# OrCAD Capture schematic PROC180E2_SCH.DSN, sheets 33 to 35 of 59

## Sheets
33 13. SOC POWER SUPPLY PMIC - 1: size C; title: SOC POWER SUPPLY PMIC - 1
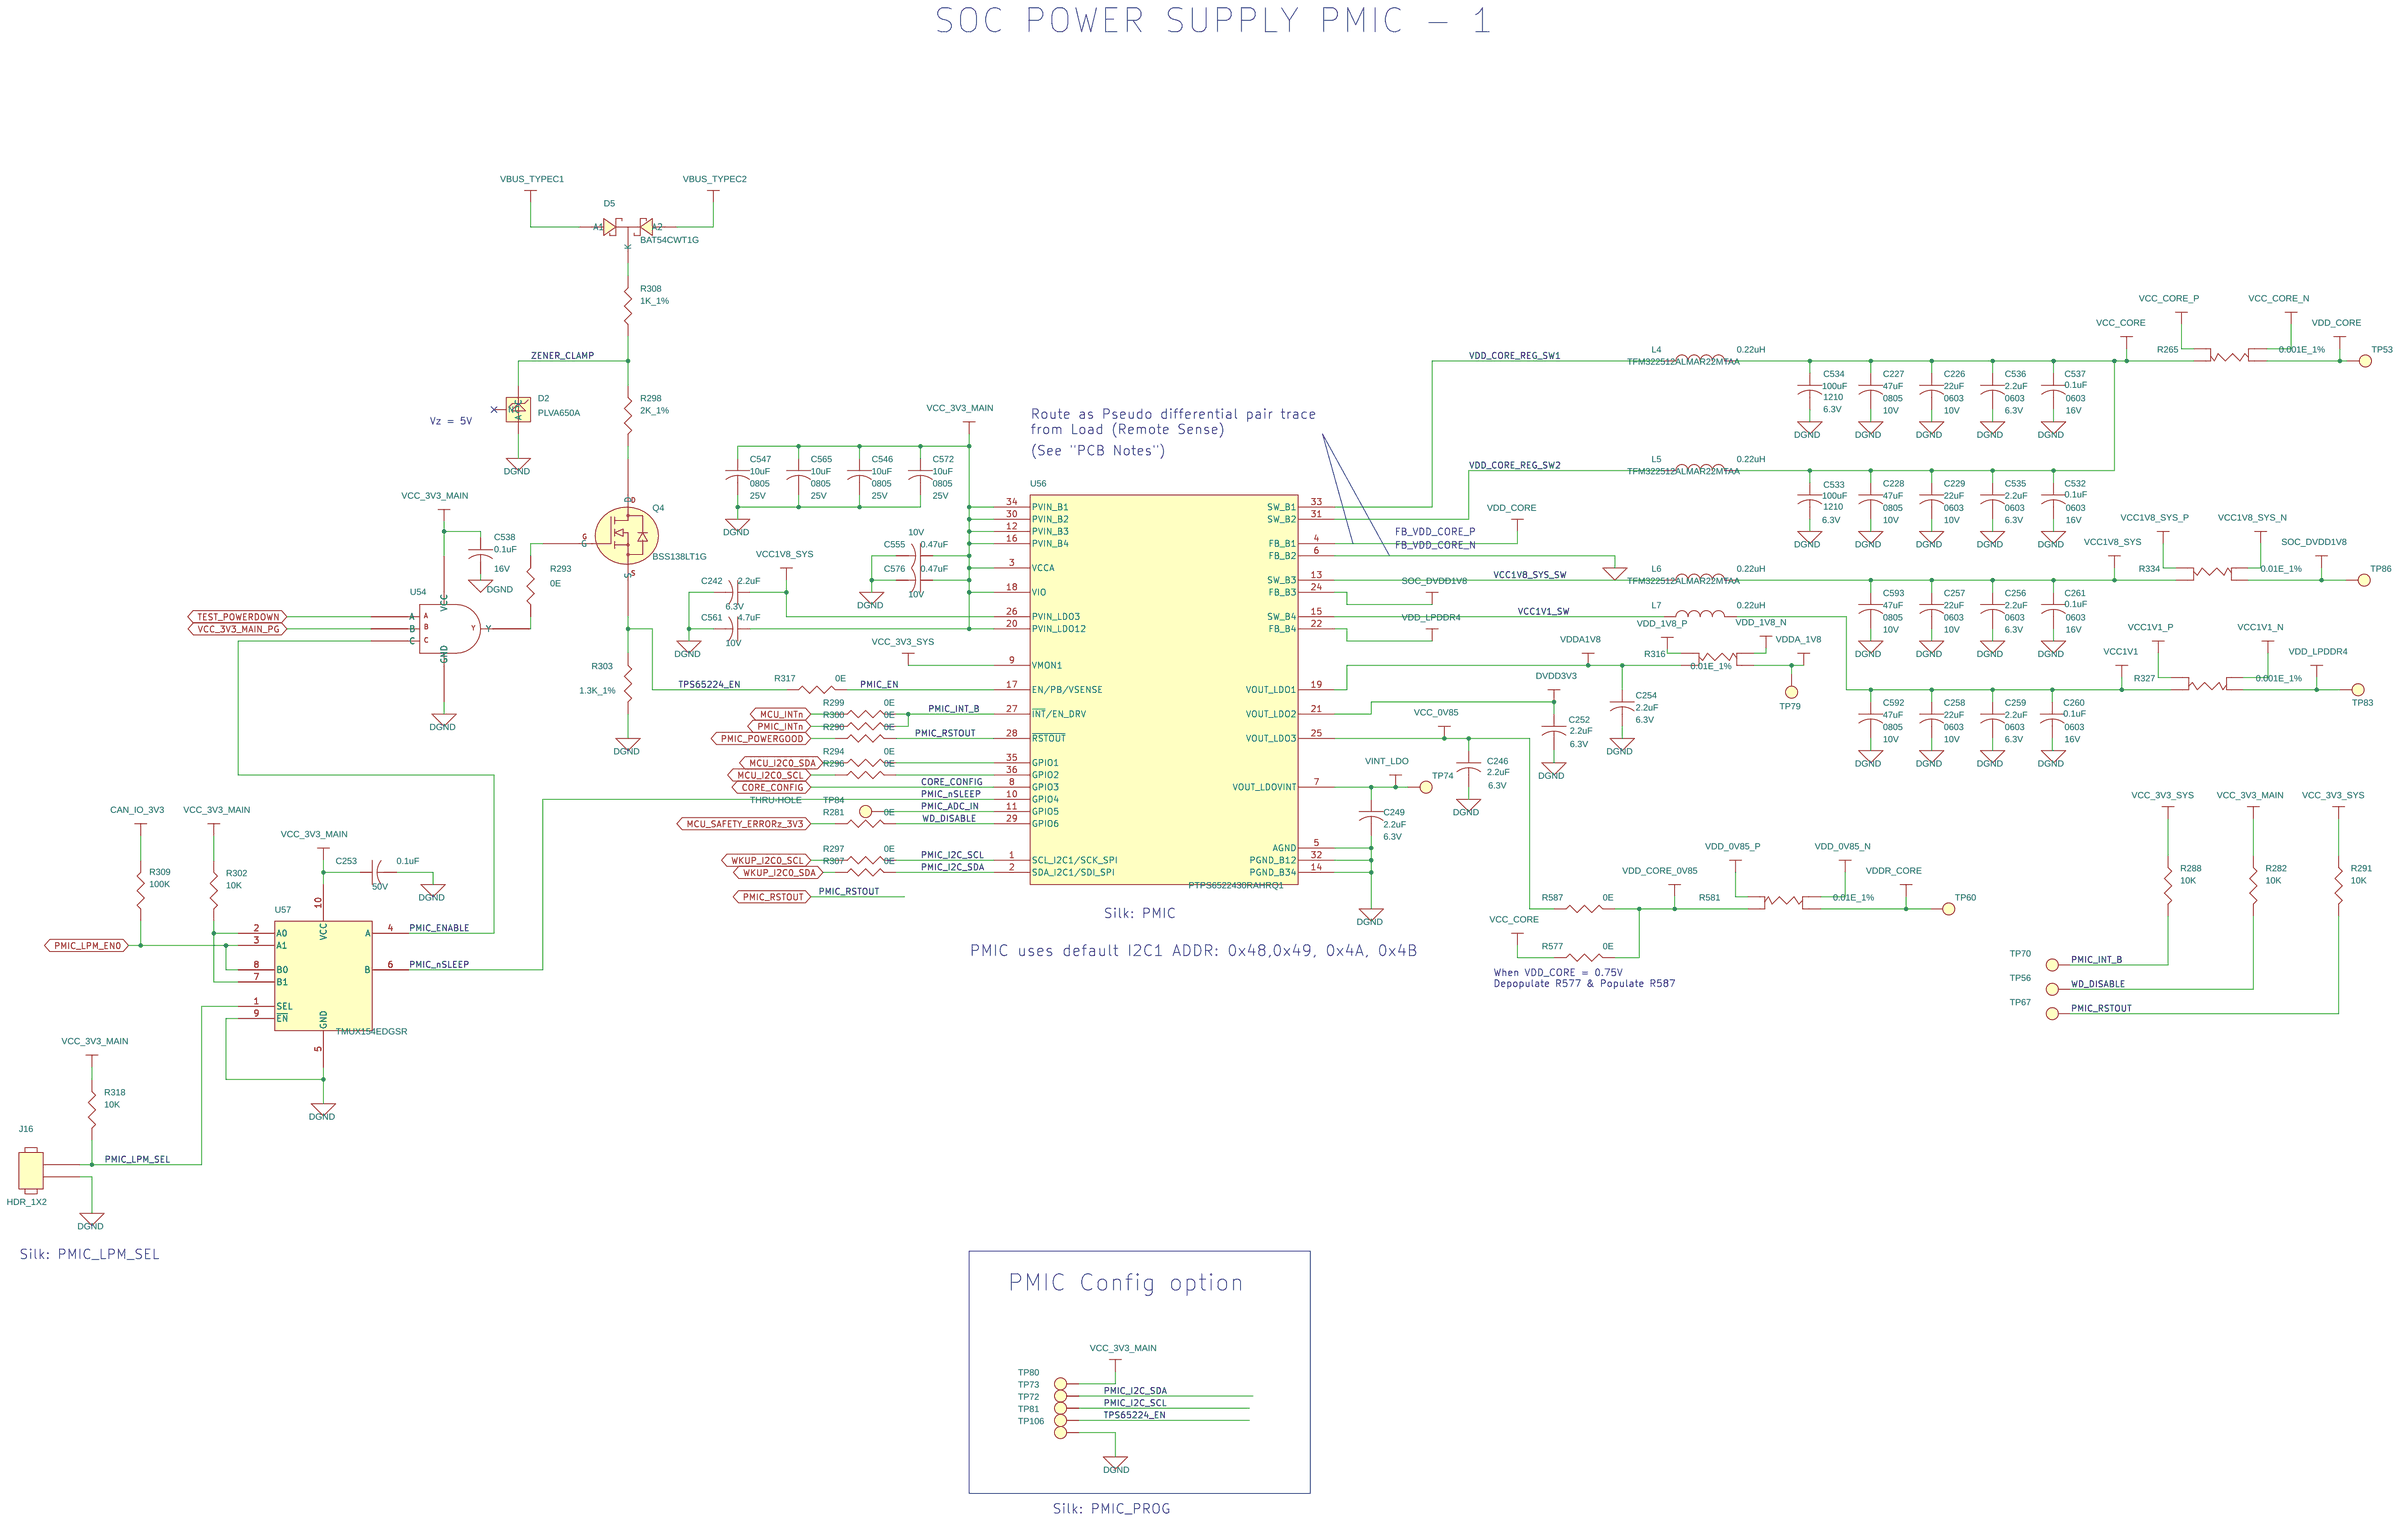
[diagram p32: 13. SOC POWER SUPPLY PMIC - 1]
34 16. SOC POWER SUPPLIES AND SUPP: size C; title: SOC POWER SUPPLIES, SUPPLY RAILS AND SOC GROUND VSS
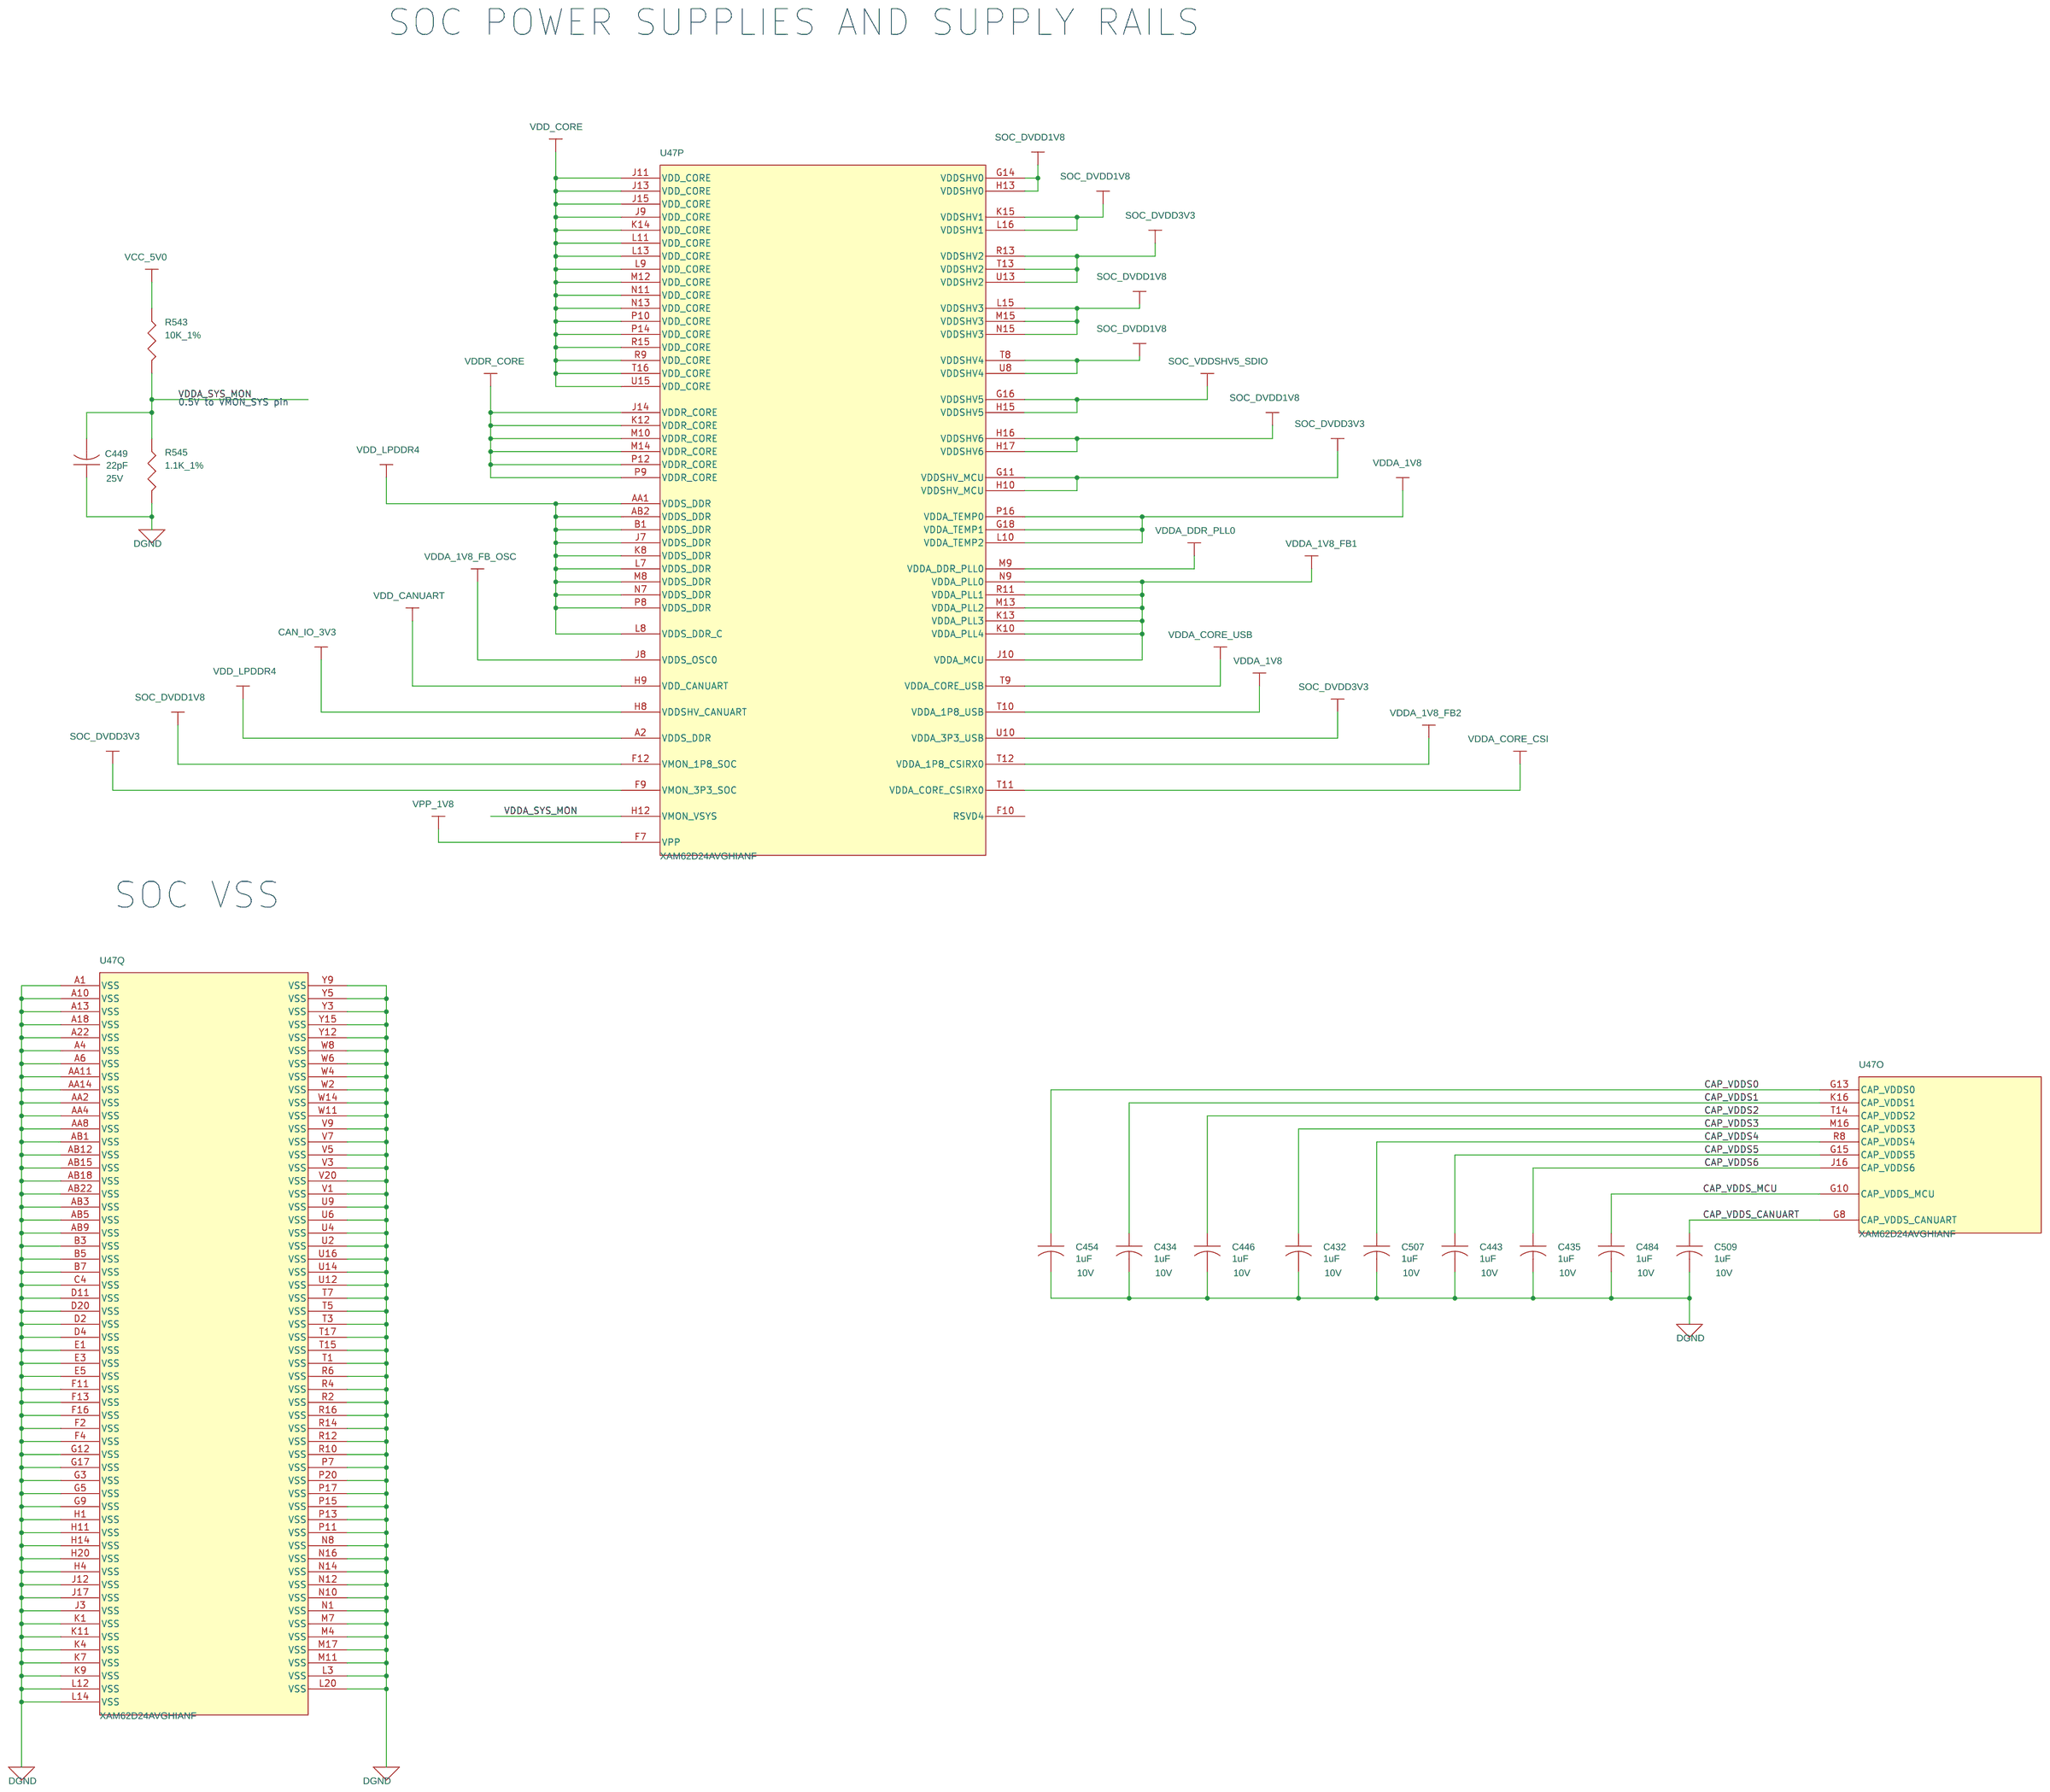
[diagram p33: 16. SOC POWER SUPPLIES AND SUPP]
35 17. SOC POWER SUPPLIES - DECAPS: size C; title: SOC POWER SUPPLIES - DECAPS 1
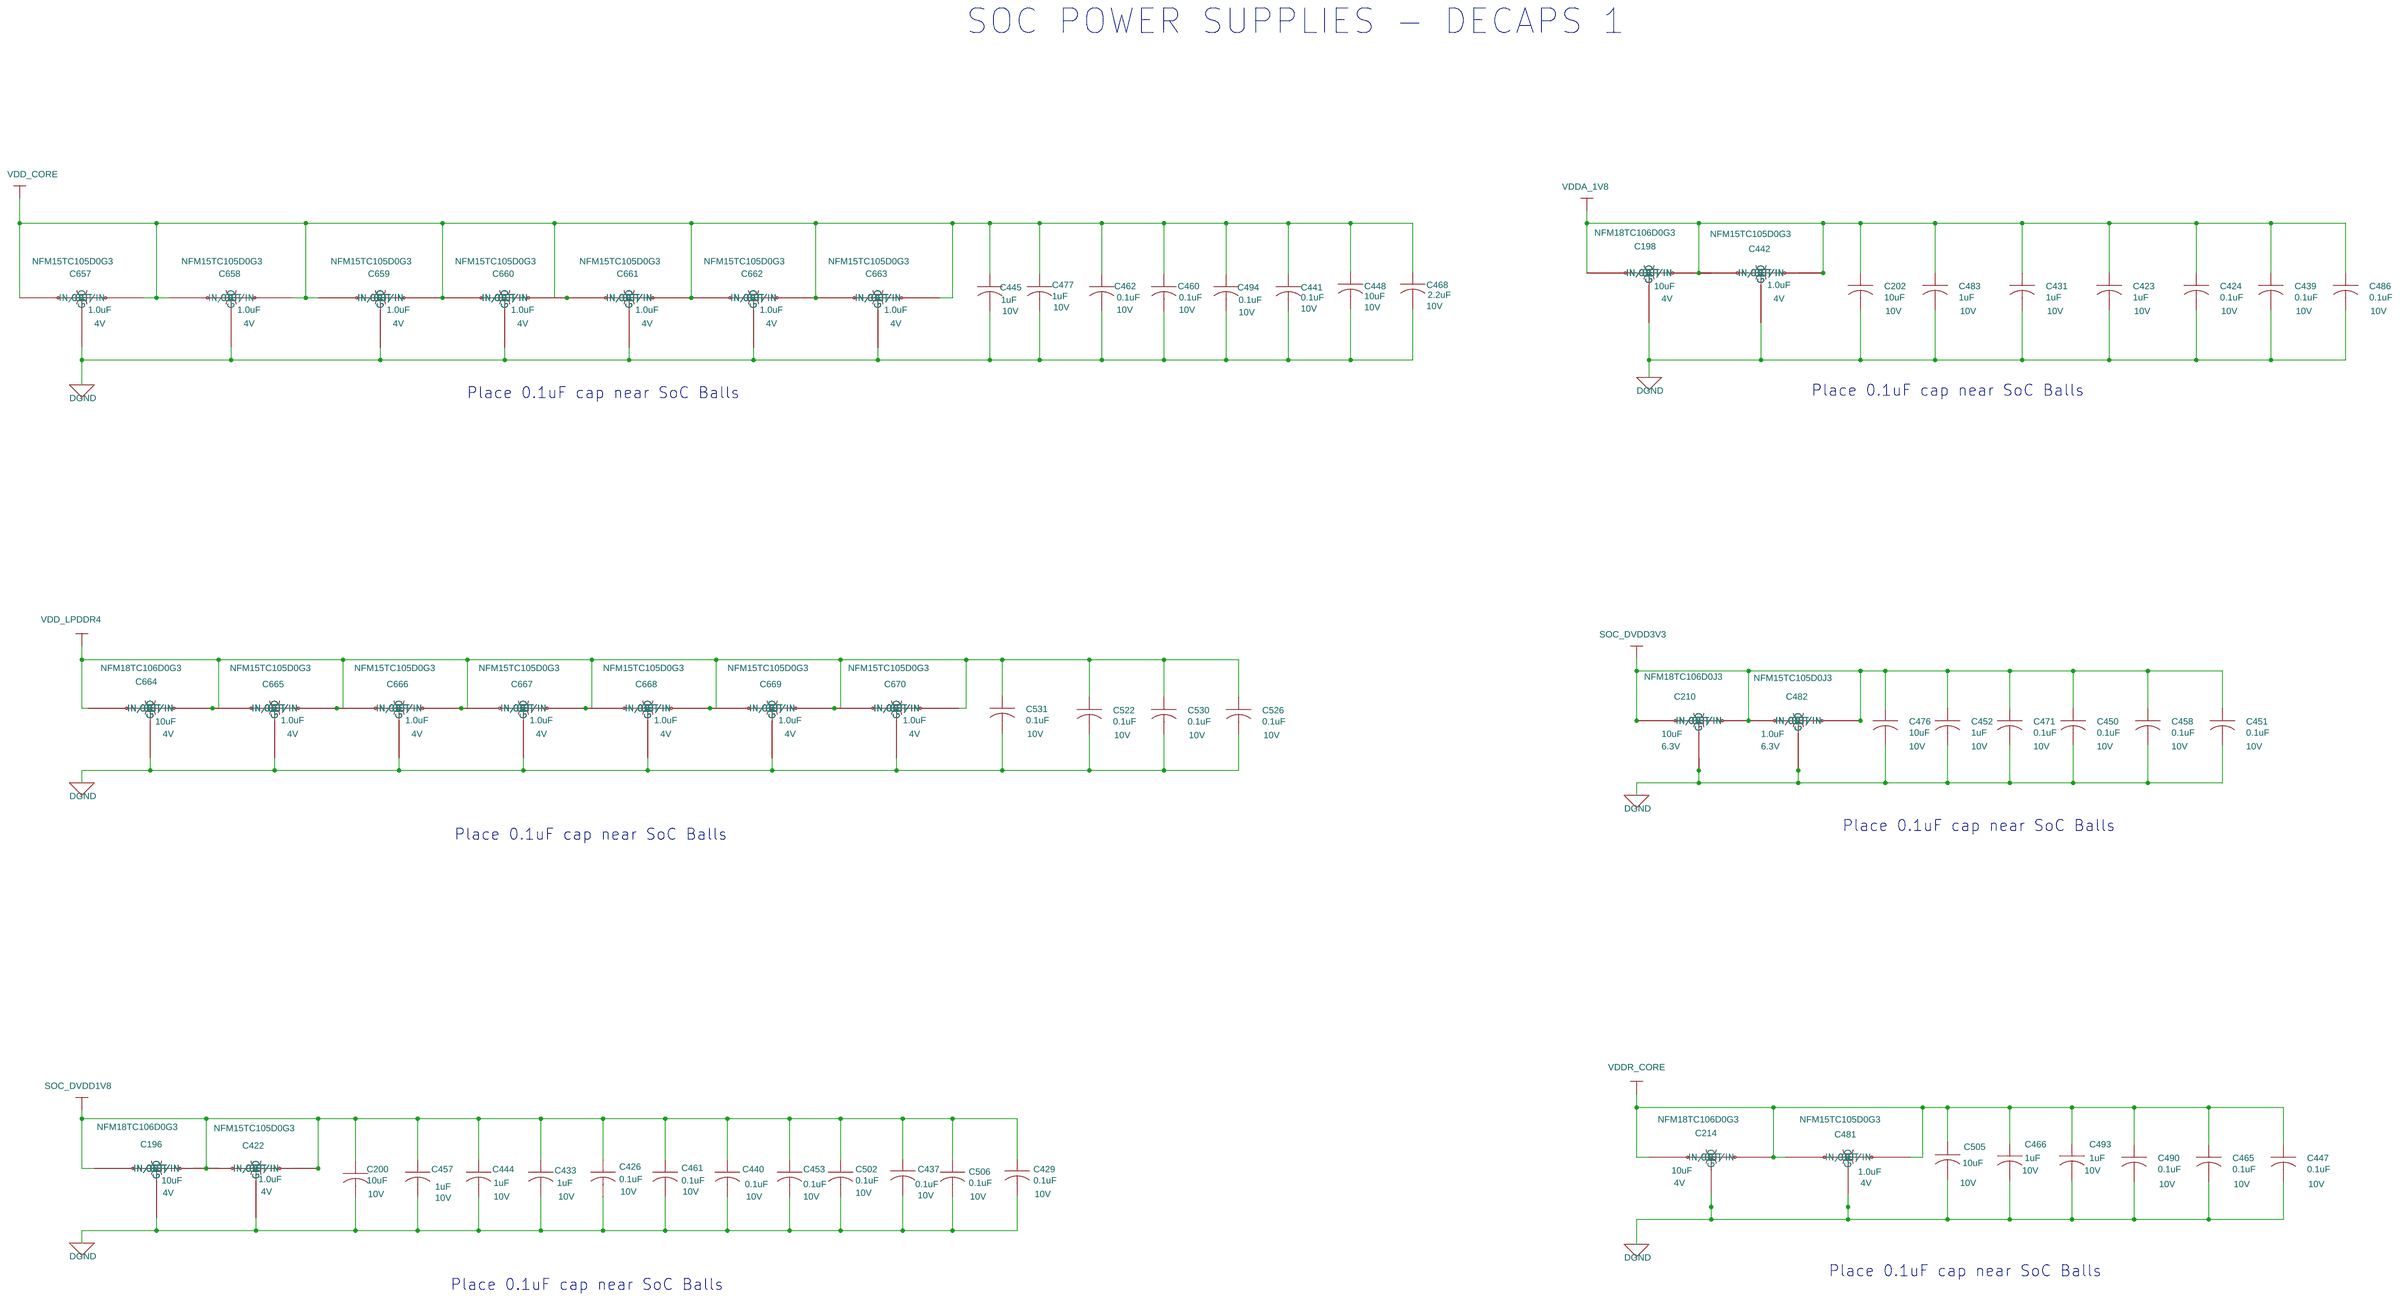
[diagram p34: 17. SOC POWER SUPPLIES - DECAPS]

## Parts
sheet 13. SOC POWER SUPPLY PMIC - 1
C226  22uF  [CAP0603_1]
C227  47uF  [CAP0805_1-5]
C228  47uF  [CAP0805_1-5]
C229  22uF  [CAP0603_1]
C242  2.2uF  [CAP0603_1]
C246  2.2uF  [CAP0603_1]
C249  2.2uF  [CAP0603_1]
C252  2.2uF  [CAP0603_1]
C253  0.1uF  [CAP0402_0-75]
C254  2.2uF  [CAP0603_1]
C256  2.2uF  [CAP0603_1]
C257  22uF  [CAP0603_1]
C258  22uF  [CAP0603_1]
C259  2.2uF  [CAP0603_1]
C260  0.1uF  [CAP0603_1]
C261  0.1uF  [CAP0603_1]
C532  0.1uF  [CAP0603_1]
C533  100uF  [CAP1210_2-75]
C534  100uF  [CAP1210_2-75]
C535  2.2uF  [CAP0603_1]
C536  2.2uF  [CAP0603_1]
C537  0.1uF  [CAP0603_1]
C538  0.1uF  [CAP0201_0-5]
C546  10uF  [CAP0805_1-5]
C547  10uF  [CAP0805_1-5]
C555  0.47uF  [CAP0402_0-75]
C561  4.7uF  [CAP0402_0-75]
C565  10uF  [CAP0805_1-5]
C572  10uF  [CAP0805_1-5]
C576  0.47uF  [CAP0402_0-75]
C592  47uF  [CAP0805_1-5]
C593  47uF  [CAP0805_1-5]
D2  PLVA650A  [DIO_SOT23_123]
D5  BAT54CWT1G  [DIO_SOT323-3_1-1]
J16  HDR_1X2  [HDR_1X2_61300211121_S_T_8-6]
L4  0.22uH  [IND1210_1-2]
L5  0.22uH  [IND1210_1-2]
L6  0.22uH  [IND1210_1-2]
L7  0.22uH  [IND1210_1-2]
Q4  BSS138LT1G  [SOT23-123_1-2]
R265  0.001E_1%  [RES_CST0612_0612-4_0-9]
R281  0E  [RES0201_0-5]
R282  10K  [RES0201_0-5]
R288  10K  [RES0201_0-5]
R290  0E  [RES0201_0-5]
R291  10K  [RES0201_0-5]
R293  0E  [RES0201_0-5]
R294  0E  [RES0201_0-5]
R296  0E  [RES0201_0-5]
R297  0E  [RES0201_0-5]
R298  2K_1%  [RES0402_0-5]
R299  0E  [RES0201_0-5]
R300  0E  [RES0201_0-5]
R302  10K  [RES0402_0-5]
R303  1.3K_1%  [RES0402_0-5]
R307  0E  [RES0201_0-5]
R308  1K_1%  [RES0402_0-5]
R309  100K  [RES0402_0-5]
R316  0.01E_1%  [RES_KRL3216T4_1206-4_0-7]
R317  0E  [RES0201_0-5]
R318  10K  [RES0402_0-5]
R327  0.001E_1%  [RES_CST0612_0612-4_0-9]
R334  0.01E_1%  [RES_KRL3216T4_1206-4_0-7]
R577  0E  [RES0603_0-75]
R581  0.01E_1%  [RES_KRL3216T4_1206-4_0-7]
R587  0E  [RES0603_0-75]
TP53  TP20_SMD  [TP20_SMD]
TP56  TP20_SMD  [TP20_SMD]
TP60  TP20_SMD  [TP20_SMD]
TP67  TP20_SMD  [TP20_SMD]
TP70  TP20_SMD  [TP20_SMD]
TP72  TP30_SMD  [TP30_SMD]
TP73  TP30_SMD  [TP30_SMD]
TP74  TP20_SMD  [TP20_SMD]
TP79  TP20_SMD  [TP20_SMD]
TP80  TP40_SMD  [TP40_SMD]
TP81  TP40_SMD  [TP40_SMD]
TP83  TP20_SMD  [TP20_SMD]
TP84  TP_CIR40D30  [TP_CIR40D30]
TP86  TP20_SMD  [TP20_SMD]
TP106  TP40_SMD  [TP40_SMD]
U54  SN74LVC1G11DRYR  [SON6_SN74LVC2G17_40X60_0-6]
U56  PTPS6522430RAHRQ1  [VQFN-HR36-35_TPS65224_240X200_1]
U57  TMUX154EDGSR  [MSOP10_19-68_120X120_1-1]
sheet 16. SOC POWER SUPPLIES AND SUPP
C432  1uF  [CAP0201_0-5]
C434  1uF  [CAP0201_0-5]
C435  1uF  [CAP0201_0-5]
C443  1uF  [CAP0201_0-5]
C446  1uF  [CAP0201_0-5]
C449  22pF  [CAP0201_0-5]
C454  1uF  [CAP0201_0-5]
C484  1uF  [CAP0201_0-5]
C507  1uF  [CAP0201_0-5]
C509  1uF  [CAP0201_0-5]
R543  10K_1%  [RES0201_0-5]
R545  1.1K_1%  [RES0402_0-5]
sheet 17. SOC POWER SUPPLIES - DECAPS
C196  10uF  [EMIFIL_NFM18C_0603_1-4]
C198  10uF  [EMIFIL_NFM18C_0603_1-4]
C200  10uF  [CAP0402_1]
C202  10uF  [CAP0402_1]
C210  10uF  [EMIFIL_NFM18C_0603_1-4]
C214  10uF  [EMIFIL_NFM18C_0603_1-4]
C422  1.0uF  [EMIFIL_NFM15CC_0402_0-5]
C423  1uF  [CAP0201_0-5]
C424  0.1uF  [CAP0201_0-5]
C426  0.1uF  [CAP0201_0-5]
C429  0.1uF  [CAP0201_0-5]
C431  1uF  [CAP0201_0-5]
C433  1uF  [CAP0201_0-5]
C437  0.1uF  [CAP0201_0-5]
C439  0.1uF  [CAP0201_0-5]
C440  0.1uF  [CAP0201_0-5]
C441  0.1uF  [CAP0201_0-5]
C442  1.0uF  [EMIFIL_NFM15CC_0402_0-5]
C444  1uF  [CAP0201_0-5]
C445  1uF  [CAP0201_0-5]
C447  0.1uF  [CAP0201_0-5]
C448  10uF  [CAP0402_1]
C450  0.1uF  [CAP0201_0-5]
C451  0.1uF  [CAP0201_0-5]
C452  1uF  [CAP0201_0-5]
C453  0.1uF  [CAP0201_0-5]
C457  1uF  [CAP0201_0-5]
C458  0.1uF  [CAP0201_0-5]
C460  0.1uF  [CAP0201_0-5]
C461  0.1uF  [CAP0201_0-5]
C462  0.1uF  [CAP0201_0-5]
C465  0.1uF  [CAP0201_0-5]
C466  1uF  [CAP0201_0-5]
C468  2.2uF  [CAP0201_0-75]
C471  0.1uF  [CAP0201_0-5]
C476  10uF  [CAP0402_1]
C477  1uF  [CAP0201_0-5]
C481  1.0uF  [EMIFIL_NFM15CC_0402_0-5]
C482  1.0uF  [EMIFIL_NFM15CC_0402_0-5]
C483  1uF  [CAP0201_0-5]
C486  0.1uF  [CAP0201_0-5]
C490  0.1uF  [CAP0201_0-5]
C493  1uF  [CAP0201_0-5]
C494  0.1uF  [CAP0201_0-5]
C502  0.1uF  [CAP0201_0-5]
C505  10uF  [CAP0402_1]
C506  0.1uF  [CAP0201_0-5]
C522  0.1uF  [CAP0201_0-5]
C526  0.1uF  [CAP0201_0-5]
C530  0.1uF  [CAP0201_0-5]
C531  0.1uF  [CAP0201_0-5]
C657  1.0uF  [EMIFIL_NFM15CC_0402_0-5]
C658  1.0uF  [EMIFIL_NFM15CC_0402_0-5]
C659  1.0uF  [EMIFIL_NFM15CC_0402_0-5]
C660  1.0uF  [EMIFIL_NFM15CC_0402_0-5]
C661  1.0uF  [EMIFIL_NFM15CC_0402_0-5]
C662  1.0uF  [EMIFIL_NFM15CC_0402_0-5]
C663  1.0uF  [EMIFIL_NFM15CC_0402_0-5]
C664  10uF  [EMIFIL_NFM18C_0603_1-4]
C665  1.0uF  [EMIFIL_NFM15CC_0402_0-5]
C666  1.0uF  [EMIFIL_NFM15CC_0402_0-5]
C667  1.0uF  [EMIFIL_NFM15CC_0402_0-5]
C668  1.0uF  [EMIFIL_NFM15CC_0402_0-5]
C669  1.0uF  [EMIFIL_NFM15CC_0402_0-5]
C670  1.0uF  [EMIFIL_NFM15CC_0402_0-5]
sheet 21. SOC RESET - 1
U47  XAM62D24AVGHIANF  [FBGA484_31-49_710X710_2-7]  (sections A,B,C,D,E,F,G,H,I,J,K,L,M,N,O,P,Q)

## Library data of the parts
C226 C229 C257 C258 = CAP: CAP CERAMIC 22uF 10V 20% X5R AUTO 0603; Chkd/date: MANIRAJA/250221; Crtd /date: ALVY/240221; Custom_Duty: 15%; Customs_HS_Code: 85369090; Distributor_name: MOUSER; Distributor_part_number: 81-GRT188R61A226ME13; Footprint Path: Y:\MIS_DATABASE\Library\ALTIUM_TOOL\PCB_FOOTPRINTS\Altium_Footprint_Lib.PcbLib; Height: 1.00MM; Library Path: Y:\MIS_DATABASE\Library\ALTIUM_TOOL\SCHEMATICS_PARTS\MS_DISCRETE_Library.schlib; Mfr_name: MURATA; Mfr_part_number: GRT188R61A226ME13D; Mistral Part No: 120021020033-R; Package: 0603; Part_type: CAPACITORS\CERAMIC; Project: TI_DRA821 SK EVM BRD; RoHS: RoHS; Temperature: -55°C+85°C; Tolerance: 20%; Voltage: 10V; Wattage: NA; Weight: NA; Datasheet: Y:\MIS_DATABASE\DATASHEETS\CAPACITORS\GRT188R61A226ME13.PDF
C227 C228 C592 C593 = CAP: CAP CERAMIC 47uF 10V 20% X5R 0805; Chkd/date: MANIRAJA/181018; Crtd /date: ALVY/181018; Custom_Duty: 15%; Customs_HS_Code: 85322990; Distributor_name: DIGIKEY; Distributor_part_number: 490-9961-1-ND; Footprint Path: Y:\MIS_DATABASE\Library\ALTIUM_TOOL\PCB_FOOTPRINTS\Altium_Footprint_Lib.PcbLib; Height: 1.45MM; Library Path: Y:\MIS_DATABASE\Library\ALTIUM_TOOL\SCHEMATICS_PARTS\MS_DISCRETE_Library.schlib; Mfr_name: MURATA; Mfr_part_number: GRM21BR61A476ME15L; Mistral Part No: 120014100011-R; Package: 0805; Part_type: CAPACITORS\CERAMIC; Project: RFID_MODULE-DESIGN; RoHS: RoHS; Temperature: -55°C+85°C; Tolerance: 20%; Voltage: 10V; Wattage: NA; Weight: 9.5mg; Datasheet: Y:\MIS_DATABASE\DATASHEETS\CAPACITORS\GRM21BR61A476ME15L.PDF
C242 C246 C249 C252 C254 C256 C259 C535 C536 = CAP: CAP CERAMIC 2.2uF 6.3V 10% X7R 0603; Chkd/date: PRADEEP/080324; Crtd /date: TAMILARASU/080324; Custom_Duty: 15%; Customs_HS_Code: 85322990; Distributor_name: NA; Distributor_part_number: NA; Footprint Path: Y:\MIS_DATABASE\Library\ALTIUM_TOOL\PCB_FOOTPRINTS\Altium_Footprint_Lib.PcbLib; Height: 0.90MM; Library Path: Y:\MIS_DATABASE\Library\ALTIUM_TOOL\SCHEMATICS_PARTS\MS_DISCRETE_Library.schlib; Mfr_name: MURATA; Mfr_part_number: GRM188R70J225KE15; Mistral Part No: 120024030008-R; Package: 0603; Part_type: CAPACITORS\CERAMIC; Project: AM62D_EVM; RoHS: RoHS; Temperature: -55°C+125°C; Tolerance: 10%; Voltage: 6.3V; Wattage: NA; Weight: 6.3mg; Datasheet: Y:\MIS_DATABASE\DATASHEETS\CAPACITORS\GRM188R70J225KE15.PDF
C253 = CAP: CAP CERAMIC 0.1uF 50V 10% X7R AUTO 0402; Chkd/date: MANIRAJA/250221; Crtd /date: ALVY/240221; Custom_Duty: 15%; Customs_HS_Code: 85322990; Distributor_name: MOUSER; Distributor_part_number: 81-GRT155R71H104KE1D; Footprint Path: Y:\MIS_DATABASE\Library\ALTIUM_TOOL\PCB_FOOTPRINTS\Altium_Footprint_Lib.PcbLib; Height: 0.55MM; Library Path: Y:\MIS_DATABASE\Library\ALTIUM_TOOL\SCHEMATICS_PARTS\MS_DISCRETE_Library.schlib; Mfr_name: MURATA; Mfr_part_number: GRT155R71H104KE01D; Mistral Part No: 120019030005-R; Package: 0402; Part_type: CAPACITORS\CERAMIC; Project: TI_DRA821 SK EVM BRD; RoHS: RoHS; Temperature: -55°C+125°C; Tolerance: 10%; Voltage: 50V; Wattage: NA; Weight: NA; Datasheet: Y:\MIS_DATABASE\DATASHEETS\CAPACITORS\GRT155R71H104KE01.PDF
C260 C261 C532 C537 = CAP: CAP CERAMIC 0.1uF 16V 10% X7R 0603; Chkd/date: MANIRAJA/290319; Crtd /date: MANIRAJA/290319; Custom_Duty: 15%; Customs_HS_Code: 85322990; Distributor_name: DIGIKEY; Distributor_part_number: 399-1096-1-ND; Footprint Path: Y:\MIS_DATABASE\Library\ALTIUM_TOOL\PCB_FOOTPRINTS\Altium_Footprint_Lib.PcbLib; Height: 0.95MM; Library Path: Y:\MIS_DATABASE\Library\ALTIUM_TOOL\SCHEMATICS_PARTS\MS_DISCRETE_Library.schlib; Mfr_name: KEMET; Mfr_part_number: C0603C104K4RACTU; Mistral Part No: 120009030076-R; Package: 0603; Part_type: CAPACITORS\CERAMIC; Project: DDAQ; RoHS: RoHS; Temperature: -55°C+125°C; Tolerance: 10%; Voltage: 16V; Wattage: NA; Weight: 2mg; Datasheet: Y:\MIS_DATABASE\DATASHEETS\CAPACITORS\KEMET-C-X7R.PDF
C533 C534 = CAP: CAP CERAMIC 100uF 6.3V 20% X5R AUTO 1210; Chkd/date: VASANTHA/290116; Crtd /date: VASANTHA/290116; Custom_Duty: 15%; Customs_HS_Code: 85322990; Distributor_name: DIGIKEY; Distributor_part_number: 490-12498-1-ND; Footprint Path: Y:\MIS_DATABASE\Library\ALTIUM_TOOL\PCB_FOOTPRINTS\Altium_Footprint_Lib.PcbLib; Height: 2.70MM; Library Path: Y:\MIS_DATABASE\Library\ALTIUM_TOOL\SCHEMATICS_PARTS\MS_DISCRETE_Library.schlib; Mfr_name: MURATA; Mfr_part_number: GRT32ER60J107ME13L; Mistral Part No: 120016010017-R; Package: 1210; Part_type: CAPACITORS\CERAMIC; Project: USHUS-2; RoHS: RoHS; Temperature: -55°C+85°C; Tolerance: 20%; Voltage: 6.3V; Wattage: NA; Weight: 16mg; Datasheet: Y:\MIS_DATABASE\DATASHEETS\CAPACITORS\GRT32ER60J107ME13L.PDF
C538 = CAP: CAP CERAMIC 0.1uF 16V 10% X7S AUTO 0201; Chkd/date: MANIRAJA/110321; Crtd /date: ALVY/110321; Custom_Duty: 15%; Customs_HS_Code: 85322990; Distributor_name: DIGIKEY; Distributor_part_number: 490-GRT033C71C104KE01DTR-ND; Footprint Path: Y:\MIS_DATABASE\Library\ALTIUM_TOOL\PCB_FOOTPRINTS\Altium_Footprint_Lib.PcbLib; Height: 0.33MM; Library Path: Y:\MIS_DATABASE\Library\ALTIUM_TOOL\SCHEMATICS_PARTS\MS_DISCRETE_Library.schlib; Mfr_name: MURATA; Mfr_part_number: GRT033C71C104KE01D; Mistral Part No: 120021030007-R; Package: 0201; Part_type: CAPACITORS\CERAMIC; Project: J7ES_SK_BRD; RoHS: RoHS; Temperature: -55°C+125°C; Tolerance: 10%; Voltage: 16V; Wattage: NA; Weight: 330mg; Datasheet: Y:\MIS_DATABASE\DATASHEETS\CAPACITORS\GRT033C71C104KE01.PDF
C546 C547 C565 C572 = CAP: CAP CERAMIC 10uF 25V 10% X7S 0805; Chkd/date: PRADEEP/130623; Crtd /date: PRADEEP/130623; Custom_Duty: 15%; Customs_HS_Code: 85322990; Distributor_name: DIGIKEY; Distributor_part_number: 490-GRT21BC71E106KE13LCT-ND; Footprint Path: Y:\MIS_DATABASE\Library\ALTIUM_TOOL\PCB_FOOTPRINTS\Altium_Footprint_Lib.PcbLib; Height: 1.45MM; Library Path: Y:\MIS_DATABASE\Library\ALTIUM_TOOL\SCHEMATICS_PARTS\MS_DISCRETE_Library.schlib; Mfr_name: MURATA; Mfr_part_number: GRT21BC71E106KE13L; Mistral Part No: 120022060025-R; Package: 0805; Part_type: CAPACITORS\CERAMIC; Project: AM62P_SK; RoHS: RoHS; Temperature: -55°C+125°C; Tolerance: 10%; Voltage: 25V; Wattage: NA; Weight: 5.5mg; Datasheet: Y:\MIS_DATABASE\DATASHEETS\CAPACITORS\GRT21BC71E106KE13L.PDF
C555 C576 = CAP: CAP CERAMIC 0.47uF 10V 10% X7R 0402; Chkd/date: MANIRAJA/310821; Crtd /date: ALVY/310821; Custom_Duty: 15%; Customs_HS_Code: 85322990; Distributor_name: DIGIKEY; Distributor_part_number: 490-14366-1-ND; Footprint Path: Y:\MIS_DATABASE\Library\ALTIUM_TOOL\PCB_FOOTPRINTS\Altium_Footprint_Lib.PcbLib; Height: 0.55MM; Library Path: Y:\MIS_DATABASE\Library\ALTIUM_TOOL\SCHEMATICS_PARTS\MS_DISCRETE_Library.schlib; Mfr_name: MURATA; Mfr_part_number: GRM155R71A474KE01D; Mistral Part No: 120021060019-R; Package: 0402; Part_type: CAPACITORS\CERAMIC; Project: TI_AM335x SK_BRD; RoHS: RoHS; Temperature: -55°C+125°C; Tolerance: 10%; Voltage: 10V; Wattage: NA; Weight: 1.5mg; Datasheet: Y:\MIS_DATABASE\DATASHEETS\CAPACITORS\GRM155R71A474KE01.PDF
C561 = CAP: CAP CERAMIC 4.7uF 10V 20% X5R AUTO 0402; Chkd/date: MANIRAJA/250221; Crtd /date: ALVY/240221; Custom_Duty: 15%; Customs_HS_Code: 85322990; Distributor_name: MOUSER; Distributor_part_number: 81-GRT155R61A475ME13; Footprint Path: Y:\MIS_DATABASE\Library\ALTIUM_TOOL\PCB_FOOTPRINTS\Altium_Footprint_Lib.PcbLib; Height: 0.65MM; Library Path: Y:\MIS_DATABASE\Library\ALTIUM_TOOL\SCHEMATICS_PARTS\MS_DISCRETE_Library.schlib; Mfr_name: MURATA; Mfr_part_number: GRT155R61A475ME13D; Mistral Part No: 120021020032-R; Package: 0402; Part_type: CAPACITORS\CERAMIC; Project: TI_DRA821 SK EVM BRD; RoHS: RoHS; Temperature: -55°C+85°C; Tolerance: 20%; Voltage: 10V; Wattage: NA; Weight: 1.5mg; Datasheet: Y:\MIS_DATABASE\DATASHEETS\CAPACITORS\GRT155R61A475ME13.PDF
D2 = DIODE_ZENER_SOT23_13: DIODE ZENER 250MW 5V SOT23-3; Chkd/date: PRAVEEN/260722; Crtd /date: PRAVEEN/260722; Custom_Duty: 15%; Customs_HS_Code: 85412900; Distributor_name: DIGIKEY; Distributor_part_number: 1727-5167-1-ND; Height: 1.10MM; Mfr_name: NEXPERIA; Mfr_part_number: PLVA650A,215; Mistral Part No: 130022070034-R; Package: SOT23-3; Part_type: DIODE\ZENER; Project: BASEBAND_HARDWARE BRD; RoHS: Pb-Free; Temperature: -65°C+150°C; Tolerance: NA; Voltage: 5V; Wattage: NA; Weight: NA; Datasheet: Y:\MIS_DATABASE\DATASHEETS\DISCRETES\DIODES\PLVA6xxA.PDF
D5 = DIODE_BAT54CW_SOT323-123: DIODE SCHOTTKY 30V 200mA SOT323-3; Chkd/date: PRADEEP/280923; Crtd /date: PRADEEP/280923; Custom_Duty: 24%; Customs_HS_Code: 85437099; Distributor_name: DIGIKEY; Distributor_part_number: BAT54CWT1GOSCT-ND; Footprint Path: Y:\MIS_DATABASE\Library\ALTIUM_TOOL\PCB_FOOTPRINTS\Altium_Footprint_Lib.PcbLib; Height: 1.10MM; Library Path: Y:\MIS_DATABASE\Library\ALTIUM_TOOL\SCHEMATICS_PARTS\MS_COMBINATIONAL_Library.schlib; Mfr_name: ONSEMI; Mistral Part No: 130023090028-R; Package: SOT323-3; Part_type: DIODE\SCHOTTKY; Project: AM62P SK; RoHS: RoHS; Temperature: -55°C+125°C; Tolerance: NA; Voltage: 30V; Wattage: NA; Weight: NA; Datasheet: Y:\MIS_DATABASE\DATASHEETS\DISCRETES\DIODES\BAT54CWT1G.PDF
J16 = HEADER_2X1: CON HDR 1X2 2.54MM PITCH ST TH; Chkd/date: MANIRAJA/031018; Crtd /date: ALVY/031018; Custom_Duty: 24%; Customs_HS_Code: 85369090; Distributor_name: DIGIKEY; Distributor_part_number: 732-5315-ND; Footprint Path: Y:\MIS_DATABASE\Library\ALTIUM_TOOL\PCB_FOOTPRINTS\Altium_Footprint_Lib.PcbLib; Height: 8.54MM; Library Path: Y:\MIS_DATABASE\Library\ALTIUM_TOOL\SCHEMATICS_PARTS\MS_CONNECTOR_Library.schlib; Mfr_name: WURTH ELECTRONICS; Mfr_part_number: 61300211121; Mistral Part No: 150018100003-R; Package: THRU-HOLE; Part_type: CONNECTOR\HEADERS; Project: ALPINE_EVM; RoHS: RoHS; Temperature: -40°C+105°C; Tolerance: NA; Voltage: NA; Wattage: NA; Weight: 120mg; Datasheet: Y:\MIS_DATABASE\DATASHEETS\CONNECTORS\6130XXX.PDF
L4-L7 = INDUCTOR: IND POWER 0.22uH 7A 20% AUTO 1210; Chkd/date: TAMILARASU/020323; Crtd /date: TAMILARASU/020323; Custom_Duty: 0.24; Customs_HS_Code: 85437099; Distributor_name: DIGIKEY; Distributor_part_number: 445-TFM322512ALMAR22MTAACT-ND; Footprint Path: Y:\MIS_DATABASE\Library\ALTIUM_TOOL\PCB_FOOTPRINTS\Altium_Footprint_Lib.PcbLib; Height: 1.20MM; Library Path: Y:\MIS_DATABASE\Library\ALTIUM_TOOL\SCHEMATICS_PARTS\MS_DISCRETE_Library.schlib; Mfr_name: TDK CORPORATION; Mfr_part_number: TFM322512ALMAR22MTAA; Mistral Part No: 130023030003-R; Package: 1210; Project: AM62P SK; RoHS: RoHS; Temperature: -55°C+150°C; Tolerance: 20%; Voltage: NA; Wattage: NA; Weight: 52mg; Datasheet: Y:\MIS_DATABASE\DATASHEETS\DISCRETES\INDUCTORS\TFM322512ALMA-SER.PDF
Q4 = MOSFET_BSS138W: IC MOSFET N-CHANNEL 50V 200mA SOT23-3; Chkd/date: MANIRAJA/250219; Crtd /date: JEBRAN/060416; Custom_Duty: 15%; Customs_HS_Code: 85423100; Distributor_name: DIGIKEY; Distributor_part_number: BSS138LT1GOSCT-ND; Footprint Path: Y:\MIS_DATABASE\Library\ALTIUM_TOOL\PCB_FOOTPRINTS\Altium_Footprint_Lib.PcbLib; Height: 1.11MM; Library Path: Y:\MIS_DATABASE\Library\ALTIUM_TOOL\SCHEMATICS_PARTS\MS_MOSFET_Library.schlib; Mfr_name: ON SEMICONDUCTOR; Mistral Part No: 142016040001-R; Package: SOT23-3; Part_type: ICS\POWER\MOSFET; Project: LRDE_ABCM; RoHS: RoHS; Temperature: -55°C+150°C; Tolerance: NA; Voltage: NA; Wattage: NA; Weight: 8mg; Datasheet: Y:\MIS_DATABASE\DATASHEETS\DISCRETES\TRANSISTORS_FETS\BSS138LT1G.PDF
R265 R327 = RESISTOR-4TERM: RES CURRENT SENSE 0.001E 1W 1% 0612-4; Chkd/date: MANIRAJA/261018; Crtd /date: ALVY/261018; Custom_Duty: 15%; Customs_HS_Code: 85332119; Distributor_name: DIGIKEY; Distributor_part_number: CST0612-FC-R001ECT-ND; Footprint Path: Y:\MIS_DATABASE\Library\ALTIUM_TOOL\PCB_FOOTPRINTS\Altium_Footprint_Lib.PcbLib; Height: 0.85MM; Library Path: Y:\MIS_DATABASE\Library\ALTIUM_TOOL\SCHEMATICS_PARTS\MS_DISCRETE_Library.schlib; Mfr_name: BOURNS; Mfr_part_number: CST0612-FC-R001E; Mistral Part No: 110018100018-R; Package: 0612-4; Part_type: RESISTORS\FIXED; Project: TI_J7ES_EVM_SOM; RoHS: RoHS; Temperature: -55°C+170°C; Tolerance: 1%; Voltage: NA; Wattage: 1W; Weight: 13.2mg; Datasheet: Y:\MIS_DATABASE\DATASHEETS\RESISTORS\CST0612-SERIES.PDF
R281 R290 R293 R294 R296 R297 R299 R300 R307 R317 = RESISTOR: RES 0E 1/20W 5% 0201; Chkd/date: NAVEED/301214; Crtd /date: MUDDU/120710; Custom_Duty: 15%; Customs_HS_Code: 85332119; Distributor_name: DIGIKEY; Distributor_part_number: 311-0.0NCT-ND; Footprint Path: Y:\MIS_DATABASE\Library\ALTIUM_TOOL\PCB_FOOTPRINTS\Altium_Footprint_Lib.PcbLib; Height: 0.26MM; Library Path: Y:\MIS_DATABASE\Library\ALTIUM_TOOL\SCHEMATICS_PARTS\MS_DISCRETE_Library.schlib; Mfr_name: YAGEO AMERICA; Mfr_part_number: RC0201JR-070RL; Mistral Part No: 110010070067-R; Package: 0201; Part_type: RESISTORS\FIXED; Project: PB_BUGBASE; RoHS: RoHS; Temperature: -55°C+125°C; Tolerance: 5%; Voltage: NA; Wattage: 1/20W; Weight: 0.17mg; Datasheet: Y:\MIS_DATABASE\DATASHEETS\RESISTORS\RCXXXXL-SER_MAR18.PDF
R282 R288 R291 = RESISTOR: RES 10K 1/20W 5% 0201; Chkd/date: MANIRAJA/050517; Crtd /date: MANIRAJA/050517; Custom_Duty: 15%; Customs_HS_Code: 85332119; Distributor_name: DIGIKEY; Distributor_part_number: 311-10KNCT-ND; Footprint Path: Y:\MIS_DATABASE\Library\ALTIUM_TOOL\PCB_FOOTPRINTS\Altium_Footprint_Lib.PcbLib; Height: 0.26MM; Library Path: Y:\MIS_DATABASE\Library\ALTIUM_TOOL\SCHEMATICS_PARTS\MS_DISCRETE_Library.schlib; Mfr_name: YAGEO AMERICA; Mfr_part_number: RC0201JR-0710KL; Mistral Part No: 110010070051-R; Package: 0201; Part_type: RESISTORS\FIXED; Project: GOLDEN-I LITE; RoHS: RoHS; Temperature: -55°C+125°C; Tolerance: 5%; Voltage: NA; Wattage: 1/20W; Weight: 0.17mg; Datasheet: Y:\MIS_DATABASE\DATASHEETS\RESISTORS\RCXXXXL-SER_MAR18.PDF
R298 = RESISTOR: RES 2K 1/10W 1% 0402; Chkd/date: SHREESHAIL/210506; Crtd /date: MAZHAR/150506; Custom_Duty: 15%; Customs_HS_Code: 85332119; Distributor_name: DIGIKEY; Distributor_part_number: P2.00KLCT-ND; Footprint Path: Y:\MIS_DATABASE\Library\ALTIUM_TOOL\PCB_FOOTPRINTS\Altium_Footprint_Lib.PcbLib; Height: 0.40MM; Library Path: Y:\MIS_DATABASE\Library\ALTIUM_TOOL\SCHEMATICS_PARTS\MS_DISCRETE_Library.schlib; Mfr_name: PANASONIC-ECG; Mfr_part_number: ERJ-2RKF2001X; Mistral Part No: 110009030606-R; Package: 0402; Part_type: RESISTORS\FIXED; Project: VOCERA; RoHS: RoHS; Temperature: -55°C+155°C; Tolerance: 1%; Voltage: NA; Wattage: 1/10W; Weight: 0.8mg; Datasheet: Y:\MIS_DATABASE\DATASHEETS\RESISTORS\PAN-ERJSER_NOV17.PDF
R302 R318 = RESISTOR: RES 10K 1/16W 5% 0402; Chkd/date: VASANTHA/061216; Crtd /date: MAZHAR/230805; Custom_Duty: 15%; Customs_HS_Code: 85332119; Distributor_name: DIGIKEY; Distributor_part_number: 311-10KJRCT-ND; Footprint Path: Y:\MIS_DATABASE\Library\ALTIUM_TOOL\PCB_FOOTPRINTS\Altium_Footprint_Lib.PcbLib; Height: 0.40MM; Library Path: Y:\MIS_DATABASE\Library\ALTIUM_TOOL\SCHEMATICS_PARTS\MS_DISCRETE_Library.schlib; Mfr_name: YAGEO AMERICA; Mfr_part_number: RC0402JR-0710KL; Mistral Part No: 110011060021-R; Package: 0402; Part_type: RESISTORS\FIXED; Project: HSE; RoHS: RoHS; Temperature: -55°C+155°C; Tolerance: 5%; Voltage: NA; Wattage: 1/16W; Weight: 0.65mg; Datasheet: Y:\MIS_DATABASE\DATASHEETS\RESISTORS\RCXXXXL-SER_MAR18.PDF
R303 = RESISTOR: RES 1.3K 1/10W 1% 0402; Chkd/date: MANIRAJA/131218; Crtd /date: ALVY/131218; Custom_Duty: 15%; Customs_HS_Code: 85332119; Distributor_name: DIGIKEY; Distributor_part_number: P1.30KLCT-ND; Footprint Path: Y:\MIS_DATABASE\Library\ALTIUM_TOOL\PCB_FOOTPRINTS\Altium_Footprint_Lib.PcbLib; Height: 0.40MM; Library Path: Y:\MIS_DATABASE\Library\ALTIUM_TOOL\SCHEMATICS_PARTS\MS_DISCRETE_Library.schlib; Mfr_name: PANASONIC-ECG; Mfr_part_number: ERJ-2RKF1301X; Mistral Part No: 110018120014-R; Package: 0402; Part_type: RESISTORS\FIXED; Project: NPOL_32SC; RoHS: RoHS; Temperature: -55°C+155°C; Tolerance: 1%; Voltage: NA; Wattage: 1/10W; Weight: 0.8mg; Datasheet: Y:\MIS_DATABASE\DATASHEETS\RESISTORS\PAN-ERJSER_NOV17.PDF
R308 = RESISTOR: RES 1K 1/10W 1% 0402; Chkd/date: VASANTHA/281216; Crtd /date: MAZHAR/150506; Custom_Duty: 15%; Customs_HS_Code: 85332119; Distributor_name: DIGIKEY; Distributor_part_number: P1.00KLCT-ND; Footprint Path: Y:\MIS_DATABASE\Library\ALTIUM_TOOL\PCB_FOOTPRINTS\Altium_Footprint_Lib.PcbLib; Height: 0.40MM; Library Path: Y:\MIS_DATABASE\Library\ALTIUM_TOOL\SCHEMATICS_PARTS\MS_DISCRETE_Library.schlib; Mfr_name: PANASONIC-ECG; Mfr_part_number: ERJ-2RKF1001X; Mistral Part No: 110009030411-R; Package: 0402; Part_type: RESISTORS\FIXED; Project: VOCERA; RoHS: RoHS; Temperature: -55°C+155°C; Tolerance: 1%; Voltage: NA; Wattage: 1/10W; Weight: 0.8mg; Datasheet: Y:\MIS_DATABASE\DATASHEETS\RESISTORS\PAN-ERJSER_NOV17.PDF
R309 = RESISTOR: RES 100K 1/10W 5% 0402; Chkd/date: VASANTHA/291216; Crtd /date: GEETHA/190406; Custom_Duty: 15%; Customs_HS_Code: 85332119; Distributor_name: DIGIKEY; Distributor_part_number: P100KJCT-ND; Footprint Path: Y:\MIS_DATABASE\Library\ALTIUM_TOOL\PCB_FOOTPRINTS\Altium_Footprint_Lib.PcbLib; Height: 0.40MM; Library Path: Y:\MIS_DATABASE\Library\ALTIUM_TOOL\SCHEMATICS_PARTS\MS_DISCRETE_Library.schlib; Mfr_name: PANASONIC-ECG; Mfr_part_number: ERJ-2GEJ104X; Mistral Part No: 110009030177-R; Package: 0402; Part_type: RESISTORS\FIXED; Project: RED EYE; RoHS: RoHS; Temperature: -55°C+155°C; Tolerance: 5%; Voltage: NA; Wattage: 1/10W; Weight: 0.8mg; Datasheet: Y:\MIS_DATABASE\DATASHEETS\RESISTORS\PAN-ERJSER_NOV17.PDF
R316 R334 R581 = RESISTOR-4TERM: RES 0.01E 1W 1% 1206-4; Chkd/date: MANIRAJA/060318; Crtd /date: MANIRAJA/060318; Custom_Duty: 15%; Customs_HS_Code: 85332119; Distributor_name: DIGIKEY; Distributor_part_number: 408-1974-1-ND; Footprint Path: Y:\MIS_DATABASE\Library\ALTIUM_TOOL\PCB_FOOTPRINTS\Altium_Footprint_Lib.PcbLib; Height: 0.70MM; Library Path: Y:\MIS_DATABASE\Library\ALTIUM_TOOL\SCHEMATICS_PARTS\MS_DISCRETE_Library.schlib; Mfr_name: SUSUMU; Mfr_part_number: KRL3216T4A-M-R010-F-T1; Mistral Part No: 110018030003-R; Package: 1206-4; Part_type: RESISTORS\FIXED; Project: GRACO SMART MODULE; RoHS: RoHS; Temperature: -55°C+155°C; Tolerance: 1%; Voltage: NA; Wattage: 1W; Weight: 16.2mg; Datasheet: Y:\MIS_DATABASE\DATASHEETS\RESISTORS\KRL-SERIES.PDF
R577 R587 = RESISTOR: RES 0E 1/10W 5% 0603; Chkd/date: MANIRAJA/051217; Crtd /date: BAVISH/180211; Custom_Duty: 15%; Customs_HS_Code: 85332119; Distributor_name: DIGIKEY; Distributor_part_number: 311-0.0GRCT-ND; Footprint Path: Y:\MIS_DATABASE\Library\ALTIUM_TOOL\PCB_FOOTPRINTS\Altium_Footprint_Lib.PcbLib; Height: 0.55MM; Library Path: Y:\MIS_DATABASE\Library\ALTIUM_TOOL\SCHEMATICS_PARTS\MS_DISCRETE_Library.schlib; Mfr_name: YAGEO AMERICA; Mfr_part_number: RC0603JR-070RL; Mistral Part No: 110011020013-R; Package: 0603; Part_type: RESISTORS\FIXED; Project: KENNEL; RoHS: RoHS; Temperature: -55°C+155°C; Tolerance: 5%; Voltage: NA; Wattage: 1/10W; Weight: 2mg; Datasheet: Y:\MIS_DATABASE\DATASHEETS\RESISTORS\RCXXXXL-SER_MAR18.PDF
TP53 TP56 TP60 TP67 TP70 TP74 TP79 TP83 TP86 = TESTPOINT: TESTPOINT CIR 20 SMD; Chkd/date: SHREESHAIL/171006; Crtd /date: MAZHAR/171006; Custom_Duty: NA; Customs_HS_Code: NA; Distributor_name: NA; Distributor_part_number: NA; Footprint Path: Y:\MIS_DATABASE\Library\ALTIUM_TOOL\PCB_FOOTPRINTS\Altium_Footprint_Lib.PcbLib; Height: NA; Library Path: Y:\MIS_DATABASE\Library\ALTIUM_TOOL\SCHEMATICS_PARTS\MS_DISCRETE_Library.schlib; MECHANICAL 3D STEP FILE: NA; Mfr_name: LOCAL; Mistral Part No: NA; Package: SMD; Project: BT MODULE_CSRBC04; RoHS: NA; Temperature: NA; Tolerance: NA; Voltage: NA; Wattage: NA; Weight: NA; Datasheet: NA
TP72 TP73 = TESTPOINT: TESTPOINT CIR 30 SMD; Chkd/date: SHREESHAIL/171006; Crtd /date: MAZHAR/171006; Custom_Duty: NA; Customs_HS_Code: NA; Distributor_name: NA; Distributor_part_number: NA; Footprint Path: Y:\MIS_DATABASE\Library\ALTIUM_TOOL\PCB_FOOTPRINTS\Altium_Footprint_Lib.PcbLib; Height: NA; Library Path: Y:\MIS_DATABASE\Library\ALTIUM_TOOL\SCHEMATICS_PARTS\MS_DISCRETE_Library.schlib; MECHANICAL 3D STEP FILE: NA; Mfr_name: LOCAL; Mistral Part No: 130009030930; Package: SMD; Project: BT MODULE_CSRBC04; RoHS: NA; Temperature: NA; Tolerance: NA; Voltage: NA; Wattage: NA; Weight: NA; Datasheet: NA
TP80 TP81 TP106 = TESTPOINT: TESTPOINT CIR 40 SMD; Chkd/date: MAZHAR/190505; Crtd /date: MAZHAR/190505; Distributor_name: NA; Distributor_part_number: NA; Footprint Path: Y:\MIS_DATABASE\Library\ALTIUM_TOOL\PCB_FOOTPRINTS\Altium_Footprint_Lib.PcbLib; Height: NA; Library Path: Y:\MIS_DATABASE\Library\ALTIUM_TOOL\SCHEMATICS_PARTS\MS_DISCRETE_Library.schlib; MECHANICAL 3D STEP FILE: NA; Mfr_name: LOCAL; Mistral Part No: 130009030933; Package: SMD; Project: RAINIER-3; RoHS: NA; Temperature: NA; Tolerance: NA; Voltage: NA; Wattage: NA; Weight: NA; Datasheet: NA
TP84 = TESTPOINT: TESTPOINT 0.75MM DRILL PTH; Crtd /date: TAMILARASU/160523; Custom_Duty: NA; Customs_HS_Code: NA; Distributor_name: NA; Distributor_part_number: NA; Footprint Path: Y:\MIS_DATABASE\Library\ALTIUM_TOOL\PCB_FOOTPRINTS\Altium_Footprint_Lib.PcbLib; Height: NA; Library Path: Y:\MIS_DATABASE\Library\ALTIUM_TOOL\SCHEMATICS_PARTS\MS_DISCRETE_Library.schlib; Mfr_name: LOCAL; Mistral Part No: NA; Package: THRU-HOLE; Project: NA; RoHS: NA; Temperature: NA; Tolerance: NA; Voltage: NA; Wattage: NA; Weight: NA; Datasheet: NA
U54 = SN74LVC1G11DCKR_SC70-6: IC SINGLE 3-INPUT POSITIVE-AND GATE SON6; Chkd/date: MANIRAJA/270121; Crtd /date: ALVY/270121; Custom_Duty: 15%; Customs_HS_Code: 85423100; Distributor_name: DIGIKEY; Distributor_part_number: 296-30120-1-ND; Footprint Path: Y:\MIS_DATABASE\Library\ALTIUM_TOOL\PCB_FOOTPRINTS\Altium_Footprint_Lib.PcbLib; Height: 0.60MM; Library Path: Y:\MIS_DATABASE\Library\ALTIUM_TOOL\SCHEMATICS_PARTS\MS_GATE_Library.schlib; Mfr_name: TEXAS INSTRUMENTS; Mistral Part No: 141021010013-R; Package: SON6; Part_type: ICS\DIGITAL\GATES; Project: AM64X_SKEVM; RoHS: RoHS; Temperature: -40°C+125°C; Tolerance: NA; Voltage: NA; Wattage: NA; Weight: 33mg; Datasheet: Y:\MIS_DATABASE\DATASHEETS\ICS\DIGITAL\GATES\SN74LVC1G_NOV16.PDF
U56 = TPS65224_VQFN-HR36: IC POWER MANAGEMENT IC (PMIC) WITH 4 BUCKS AND 3 LDOS FOR SAFETYRELEVANT AUTOMOTIVE APPLICATIONS VQFN-HR36-35; Chkd/date: PRAVEEN/210223; Crtd /date: TAMILARASU/210223; Custom_Duty: 15%; Customs_HS_Code: 85423100; Distributor_name: NA; Distributor_part_number: NA; Height: 1.00MM; MECHANICAL 3D STEP FILE: NA; Mfr_name: TEXAS INSTRUMENTS; Mistral Part No: 142023060009-R; Package: VQFN-HR36-35; Part_type: ICS\POWER\MANAGEMENT; Project: AM62P_SK_BRD; RoHS: NA; Temperature: -40°C+125°C; Tolerance: NA; Voltage: NA; Wattage: NA; Weight: NA; Datasheet: Y:\MIS_DATABASE\DATASHEETS\ICS\POWER\TPS65224-Q1.PDF
U57 = TMUX154EDGSR_VSSOP10: IC ESD PROTECTED 2-CH 2:1 SWITCH WITH POWERED-OFF PROTECTION VSSOP10; Chkd/date: MANIRAJA/040918; Crtd /date: MANIRAJA/040918; Custom_Duty: 15%; Customs_HS_Code: 85423100; Distributor_name: DIGIKEY; Distributor_part_number: 296-48347-1-ND; Footprint Path: Y:\MIS_DATABASE\Library\ALTIUM_TOOL\PCB_FOOTPRINTS\Altium_Footprint_Lib.PcbLib; Height: 1.10MM; Library Path: Y:\MIS_DATABASE\Library\ALTIUM_TOOL\SCHEMATICS_PARTS\MS_ANALOG-APPLICATION_Library.schlib; Mfr_name: TEXAS INSTRUMENTS; Mistral Part No: 140118090001-R; Package: VSSOP10; Part_type: ICS\ANALOG\SWITCH; Project: DLRL_DFP_ATRUC CARD; RoHS: RoHS; Temperature: -40°C+85°C; Tolerance: NA; Voltage: NA; Wattage: NA; Weight: NA; Datasheet: Y:\MIS_DATABASE\DATASHEETS\ICS\ANALOG\TMUX154EXXX.PDF
C423 C431-C435 C443-C446 C452 C454 C457 C466 C477 C483 C484 C493 C507 C509 = CAP: CAP CERAMIC 1uF 10V 20% X5R 0201; Chkd/date: NAVEED/070415; Crtd /date: VASANTHA/230314; Custom_Duty: 15%; Customs_HS_Code: 85322990; Distributor_name: DIGIKEY; Distributor_part_number: 1276-1324-1-ND; Footprint Path: Y:\MIS_DATABASE\Library\ALTIUM_TOOL\PCB_FOOTPRINTS\Altium_Footprint_Lib.PcbLib; Height: 0.35MM; Library Path: Y:\MIS_DATABASE\Library\ALTIUM_TOOL\SCHEMATICS_PARTS\MS_DISCRETE_Library.schlib; Mfr_name: SAMSUNG; Mfr_part_number: CL03A105MP3NSNC; Mistral Part No: 120015030003-R; Package: 0201; Part_type: CAPACITORS\CERAMIC; Project: DUET BOARDS; RoHS: RoHS; Temperature: -55°C+85°C; Tolerance: 20%; Voltage: 10V; Wattage: NA; Weight: 0.17mg; Datasheet: Y:\MIS_DATABASE\DATASHEETS\CAPACITORS\CL03A105MP3NSNC.PDF
C449 = CAP: CAP CERAMIC 22pF 25V 1% C0G(NP0) AUTO 0201; Chkd/date: MANIRAJA/311221; Crtd /date: ALVY/301221; Custom_Duty: 15%; Customs_HS_Code: 85322990; Distributor_name: MOUSER; Distributor_part_number: 81-GRT0335C1E220FA2D; Footprint Path: Y:\MIS_DATABASE\Library\ALTIUM_TOOL\PCB_FOOTPRINTS\Altium_Footprint_Lib.PcbLib; Height: 0.33MM; Library Path: Y:\MIS_DATABASE\Library\ALTIUM_TOOL\SCHEMATICS_PARTS\MS_DISCRETE_Library.schlib; Mfr_name: MURATA; Mfr_part_number: GRT0335C1E220FA02D; Mistral Part No: 120021120014-R; Package: 0201; Part_type: CAPACITORS\CERAMIC; Project: AM62Q_SKEVM_BRD; RoHS: RoHS; Temperature: -55°C+125°C; Tolerance: 1%; Voltage: 25V; Wattage: NA; Weight: 0.33mg; Datasheet: Y:\MIS_DATABASE\DATASHEETS\CAPACITORS\GRT0335C1E220FA02.PDF
R543 = RESISTOR: RES 10K 1/20W 1% 0201; Chkd/date: VASANTHA/270117; Crtd /date: MANIRAJA/270117; Custom_Duty: 15%; Customs_HS_Code: 85332119; Distributor_name: DIGIKEY; Distributor_part_number: 311-10.0KMCT-ND; Footprint Path: Y:\MIS_DATABASE\Library\ALTIUM_TOOL\PCB_FOOTPRINTS\Altium_Footprint_Lib.PcbLib; Height: 0.26MM; Library Path: Y:\MIS_DATABASE\Library\ALTIUM_TOOL\SCHEMATICS_PARTS\MS_DISCRETE_Library.schlib; Mfr_name: YAGEO AMERICA; Mfr_part_number: RC0201FR-0710KL; Mistral Part No: 110011040018-R; Package: 0201; Part_type: RESISTORS\FIXED; Project: GOLDEN-I LITE; RoHS: RoHS; Temperature: -55°C+125°C; Tolerance: 1%; Voltage: NA; Wattage: 1/20W; Weight: 0.17mg; Datasheet: Y:\MIS_DATABASE\DATASHEETS\RESISTORS\RCXXXXL-SER_MAR18.PDF
R545 = RESISTOR: RES 1.1K 1/16W 1% 0402; Chkd/date: MANIRAJA/081020; Crtd /date: ALVY/081020; Custom_Duty: 15%; Customs_HS_Code: 85332119; Distributor_name: DIGIKEY; Distributor_part_number: 541-1.10KLCT-ND; Footprint Path: Y:\MIS_DATABASE\Library\ALTIUM_TOOL\PCB_FOOTPRINTS\Altium_Footprint_Lib.PcbLib; Height: 0.40MM; Library Path: Y:\MIS_DATABASE\Library\ALTIUM_TOOL\SCHEMATICS_PARTS\MS_DISCRETE_Library.schlib; Mfr_name: VISHAY; Mfr_part_number: CRCW04021K10FKED; Mistral Part No: 110010120009-R; Package: 0402; Part_type: RESISTORS\FIXED; Project: VAGG_SBC_BRD; RoHS: RoHS; Temperature: -55°C+155°C; Tolerance: 1%; Voltage: NA; Wattage: 1/16W; Weight: 0.65mg; Datasheet: Y:\MIS_DATABASE\DATASHEETS\RESISTORS\CRCW0603.PDF
C196 C198 C214 C664 = FILTER3_NFM18: PASSIVE FILTER EMI 10uF 20% 4V 0603; Chkd/date: PRADEEP/080324; Crtd /date: TAMILARASU/080324; Custom_Duty: 15%; Customs_HS_Code: 85439000; Distributor_name: NA; Distributor_part_number: NA; Footprint Path: Y:\MIS_DATABASE\Library\ALTIUM_TOOL\PCB_FOOTPRINTS\Altium_Footprint_Lib.PcbLib; Height: 1.35MM; Library Path: Y:\MIS_DATABASE\Library\ALTIUM_TOOL\SCHEMATICS_PARTS\MS_FILTER_Library.schlib; Mfr_name: MURATA; Mfr_part_number: NFM18TC106D0G3; Mistral Part No: 130024030008-R; Package: 0603; Part_type: FILTER; Project: AM62D_EVM; RoHS: RoHS; Temperature: -55°C+125°C; Tolerance: 0.2; Voltage: 4V; Wattage: NA; Weight: NA; Datasheet: Y:\MIS_DATABASE\DATASHEETS\DISCRETES\INDUCTORS\NFM18TC106D0G3.PDF
C200 C202 C448 C476 C505 = CAP: CAP CERAMIC 10uF 10V 20% X5R 0402; Chkd/date: MANIRAJA/150219; Crtd /date: ALVY/150219; Custom_Duty: 15%; Customs_HS_Code: 85322990; Distributor_name: DIGIKEY; Distributor_part_number: 1276-6830-1-ND; Footprint Path: Y:\MIS_DATABASE\Library\ALTIUM_TOOL\PCB_FOOTPRINTS\Altium_Footprint_Lib.PcbLib; Height: 0.90MM; Library Path: Y:\MIS_DATABASE\Library\ALTIUM_TOOL\SCHEMATICS_PARTS\MS_DISCRETE_Library.schlib; Mfr_name: SAMSUNG; Mfr_part_number: CL05A106MP8NUB8; Mistral Part No: 120019020008-R; Package: 0402; Part_type: CAPACITORS\CERAMIC; Project: TI_60GHz-AOP; RoHS: RoHS; Temperature: -55°C+85°C; Tolerance: 20%; Voltage: 10V; Wattage: NA; Weight: NA; Datasheet: Y:\MIS_DATABASE\DATASHEETS\CAPACITORS\CL05A106MP8NUB8.PDF
C210 = FILTER3_NFM18: PASSIVE FILTER EMI 10uF 6.3V 0603; Chkd/date: PRADEEP/130623; Crtd /date: PRADEEP/130623; Custom_Duty: 24%; Customs_HS_Code: 85439000; Distributor_name: NA; Distributor_part_number: NA; Footprint Path: Y:\MIS_DATABASE\Library\ALTIUM_TOOL\PCB_FOOTPRINTS\Altium_Footprint_Lib.PcbLib; Height: 1.35MM; Library Path: Y:\MIS_DATABASE\Library\ALTIUM_TOOL\SCHEMATICS_PARTS\MS_FILTER_Library.schlib; Mfr_name: MURATA; Mfr_part_number: NFM18TC106D0J3; Mistral Part No: 130023060021-R; Package: 0603; Part_type: FILTER; Project: AM62P_SK; RoHS: RoHS; Temperature: -55°C+125°C; Tolerance: NA; Voltage: 6.3V; Wattage: NA; Weight: NA; Datasheet: Y:\MIS_DATABASE\DATASHEETS\DISCRETES\INDUCTORS\NFM18TC106D0J3.PDF
C422 C442 C481 C657-C663 C665-C670 = FILTER3_NFM18: PASSIVE FILTER EMI 1.0uF 20% 4V 0402; Chkd/date: PRADEEP/080324; Crtd /date: TAMILARASU/080324; Custom_Duty: 15%; Customs_HS_Code: 85439000; Distributor_name: NA; Distributor_part_number: NA; Footprint Path: Y:\MIS_DATABASE\Library\ALTIUM_TOOL\PCB_FOOTPRINTS\Altium_Footprint_Lib.PcbLib; Height: 0.50MM; Library Path: Y:\MIS_DATABASE\Library\ALTIUM_TOOL\SCHEMATICS_PARTS\MS_FILTER_Library.schlib; Mfr_name: MURATA; Mfr_part_number: NFM15TC105D0G3; Mistral Part No: 130024030009-R; Package: 0402; Part_type: FILTER; Project: AM62D_EVM; RoHS: RoHS; Temperature: -55°C+125°C; Tolerance: 0.2; Voltage: 4V; Wattage: NA; Weight: NA; Datasheet: Y:\MIS_DATABASE\DATASHEETS\DISCRETES\INDUCTORS\NFM15TC105D0G3.PDF
C424 C426 C429 C437 C439-C441 C447 C450 C451 C453 C458 C460-C462 C465 C471 C486 C490 C494 C502 C506 C522 C526 C530 C531 = CAP: CAP CERAMIC 0.1uF 10V 10% X5R 0201; Chkd/date: MANIRAJA/290421; Crtd /date: ALVY/290421; Custom_Duty: 15%; Customs_HS_Code: 85322990; Distributor_name: DIGIKEY; Distributor_part_number: 1276-1115-1-ND; Footprint Path: Y:\MIS_DATABASE\Library\ALTIUM_TOOL\PCB_FOOTPRINTS\Altium_Footprint_Lib.PcbLib; Height: 0.33MM; Library Path: Y:\MIS_DATABASE\Library\ALTIUM_TOOL\SCHEMATICS_PARTS\MS_DISCRETE_Library.schlib; Mfr_name: SAMSUNG; Mfr_part_number: CL03A104KP3NNNC; Mistral Part No: 120009050017-R; Package: 0201; Part_type: CAPACITORS\CERAMIC; Project: SRMS-SAR_BRD; RoHS: RoHS; Temperature: -55°C+85°C; Tolerance: 10%; Voltage: 10V; Wattage: NA; Weight: 0.33mg; Datasheet: Y:\MIS_DATABASE\DATASHEETS\CAPACITORS\CL03A104KP3NNNC.PDF
C468 = CAP: CAP CERAMIC 2.2uF 10V 20% X5R 0201; Chkd/date: PRADEEP/130623; Crtd /date: PRADEEP/130623; Custom_Duty: 15%; Customs_HS_Code: 85322990; Distributor_name: NA; Distributor_part_number: NA; Footprint Path: Y:\MIS_DATABASE\Library\ALTIUM_TOOL\PCB_FOOTPRINTS\Altium_Footprint_Lib.PcbLib; Height: 0.55MM; Library Path: Y:\MIS_DATABASE\Library\ALTIUM_TOOL\SCHEMATICS_PARTS\MS_DISCRETE_Library.schlib; Mfr_name: MURATA; Mfr_part_number: GRM035R61A225ME01; Mistral Part No: 120022060026-R; Package: 0201; Part_type: CAPACITORS\CERAMIC; Project: AM62P_SK; RoHS: RoHS; Temperature: -55°C+85°C; Tolerance: 20%; Voltage: 10V; Wattage: NA; Weight: 0.57mg; Datasheet: Y:\MIS_DATABASE\DATASHEETS\CAPACITORS\GRM035R61A225ME01.PDF
C482 = FILTER3_NFM18: PASSIVE FILTER EMI 1.0uF 6.3V 0402; Chkd/date: PRADEEP/130623; Crtd /date: PRADEEP/130623; Custom_Duty: 24%; Customs_HS_Code: 85439000; Distributor_name: NA; Distributor_part_number: NA; Footprint Path: Y:\MIS_DATABASE\Library\ALTIUM_TOOL\PCB_FOOTPRINTS\Altium_Footprint_Lib.PcbLib; Height: 0.50MM; Library Path: Y:\MIS_DATABASE\Library\ALTIUM_TOOL\SCHEMATICS_PARTS\MS_FILTER_Library.schlib; Mfr_name: MURATA; Mfr_part_number: NFM15TC105D0J3; Mistral Part No: 130023060020-R; Package: 0402; Part_type: FILTER; Project: AM62P_SK; RoHS: RoHS; Temperature: -55°C+125°C; Tolerance: NA; Voltage: 6.3V; Wattage: NA; Weight: NA; Datasheet: Y:\MIS_DATABASE\DATASHEETS\DISCRETES\INDUCTORS\NFM15TC105D0J3.PDF
U47 = AM62D_EVM_SOC_FCBGA484: IC AM62D EVM SoC MICROPROCESSOR FCBGA484; Chkd/date: PRADEEP/010424; Crtd /date: PRADEEP/010424; Custom_Duty: 15%; Customs_HS_Code: 85423100; Distributor_name: NA; Distributor_part_number: NA; Footprint Path: Y:\MIS_DATABASE\Library\ALTIUM_TOOL\PCB_FOOTPRINTS\Altium_Footprint_Lib.PcbLib; Height: 2.65MM; Library Ref: AM62D_EVM_SoC_FCBGA484; Mfr_name: TEXAS INSTRUMENTS; Mistral Part No: 141224040001-R; Package: FCBGA484; Part_type: ICS\DIGITAL\MICROPROCESSOR; Project: AM62D_EVM; RoHS: NA; Temperature: NA; Tolerance: NA; Voltage: NA; Wattage: NA; Weight: NA; Datasheet: Y:\MIS_DATABASE\DATASHEETS\ICS\DIGITAL\MICROCONTROLLER\AM62A_SK_EVM.PDF

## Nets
DGND: C196.2(GND) C198.2(GND) C200.2 C202.2 C210.2(GND) C214.2(GND) C226.2 C227.2 C228.2 C229.2 C242.2 C246.2 C249.2 C252.2 C253.2 C254.2 C256.2 C257.2 C258.2 C259.2 C260.2 C261.2 C422.2(GND) C423.2 C424.2 C426.2 C429.2 C431.2 C432.2 C433.2 C434.2 C435.2 C437.2 C439.2 C440.2 C441.2 C442.2(GND) C443.2 C444.2 C445.2 C446.2 C447.2 C448.2 C449.1 C450.2 C451.2 C452.2 C453.2 C454.2 C457.2 C458.2 C460.2 C461.2 C462.2 C465.2 C466.2 C468.2 C471.2 C476.2 C477.2 C481.2(GND) C482.2(GND) C483.2 C484.2 C486.2 C490.2 C493.2 C494.2 C502.2 C505.2 C506.2 C507.2 C509.2 C522.2 C526.2 C530.2 C531.2 C532.2 C533.2 C534.2 C535.2 C536.2 C537.2 C538.2 C546.2 C547.2 C555.2 C561.2 C565.2 C572.2 C576.2 C592.2 C593.2 C657.2(GND) C658.2(GND) C659.2(GND) C660.2(GND) C661.2(GND) C662.2(GND) C663.2(GND) C664.2(GND) C665.2(GND) C666.2(GND) C667.2(GND) C668.2(GND) C669.2(GND) C670.2(GND) D2.1(A) J16.2 R303.2 R545.2 TP106.1(TP) U47.A1(VSS) U47.A4(VSS) U47.A6(VSS) U47.A10(VSS) U47.A13(VSS) U47.A18(VSS) U47.A22(VSS) U47.AA2(VSS) U47.AA4(VSS) U47.AA8(VSS) U47.AA11(VSS) U47.AA14(VSS) U47.AB1(VSS) U47.AB3(VSS) U47.AB5(VSS) U47.AB9(VSS) U47.AB12(VSS) U47.AB15(VSS) U47.AB18(VSS) U47.AB22(VSS) U47.B3(VSS) U47.B5(VSS) U47.B7(VSS) U47.C4(VSS) U47.D2(VSS) U47.D4(VSS) U47.D11(VSS) U47.D20(VSS) U47.E1(VSS) U47.E3(VSS) U47.E5(VSS) U47.F2(VSS) U47.F4(VSS) U47.F11(VSS) U47.F13(VSS) U47.F16(VSS) U47.G3(VSS) U47.G5(VSS) U47.G9(VSS) U47.G12(VSS) U47.G17(VSS) U47.H1(VSS) U47.H4(VSS) U47.H11(VSS) U47.H14(VSS) U47.H20(VSS) U47.J3(VSS) U47.J12(VSS) U47.J17(VSS) U47.K1(VSS) U47.K4(VSS) U47.K7(VSS) U47.K9(VSS) U47.K11(VSS) U47.L3(VSS) U47.L12(VSS) U47.L14(VSS) U47.L20(VSS) U47.M4(VSS) U47.M7(VSS) U47.M11(VSS) U47.M17(VSS) U47.N1(VSS) U47.N8(VSS) U47.N10(VSS) U47.N12(VSS) U47.N14(VSS) U47.N16(VSS) U47.P7(VSS) U47.P11(VSS) U47.P13(VSS) U47.P15(VSS) U47.P17(VSS) U47.P20(VSS) U47.R2(VSS) U47.R4(VSS) U47.R6(VSS) U47.R10(VSS) U47.R12(VSS) U47.R14(VSS) U47.R16(VSS) U47.T1(VSS) U47.T3(VSS) U47.T5(VSS) U47.T7(VSS) U47.T15(VSS) U47.T17(VSS) U47.U2(VSS) U47.U4(VSS) U47.U6(VSS) U47.U9(VSS) U47.U12(VSS) U47.U14(VSS) U47.U16(VSS) U47.V1(VSS) U47.V3(VSS) U47.V5(VSS) U47.V7(VSS) U47.V9(VSS) U47.V20(VSS) U47.W2(VSS) U47.W4(VSS) U47.W6(VSS) U47.W8(VSS) U47.W11(VSS) U47.W14(VSS) U47.Y3(VSS) U47.Y5(VSS) U47.Y9(VSS) U47.Y12(VSS) U47.Y15(VSS) U54.2(GND) U56.5(AGND) U56.6(FB_B2) U56.14(PGND_B34) U56.32(PGND_B12) U57.5(GND) U57.9(~{EN}) ; also on sheet 1 2 3 4 5 6 7 8 9 10 12 13 14 16 17 18 19 20 21 22 31 32 36 37 38 39 40 41 42 43 44 45 46 47 48 49 50 51 52 53 54 55 56 57 58
DVDD3V3: C252.1 U56.21(VOUT_LDO2) ; also on sheet 14
VBUS_TYPEC1: D5.1(A1) ; also on sheet 12 31
VBUS_TYPEC2: D5.2(A2) ; also on sheet 31 52
VCC1V1: C258.1 C259.1 C260.1 C592.1 L7.2 R327.1
VCC1V1_N: R327.3 ; also on sheet 18
VCC1V1_P: R327.2 ; also on sheet 18
VCC1V1_SW: L7.1 U56.15(SW_B4)
VCC1V8_SYS: C242.1 C256.1 C257.1 C261.1 C593.1 L6.2 R334.2 U56.26(PVIN_LDO3) ; also on sheet 1 2 4 6 7 10 20 21 22 37 38 39 42 43 49 50 52 53 54 55 56 57 58
VCC1V8_SYS_N: R334.4 ; also on sheet 18
VCC1V8_SYS_P: R334.1 ; also on sheet 18
VCC1V8_SYS_SW: L6.1 U56.13(SW_B3)
VCC_0V85: C246.1 R587.1 U56.25(VOUT_LDO3)
VCC_3V3_MAIN: C253.1 C538.1 C546.1 C547.1 C555.1 C561.1 C565.1 C572.1 C576.1 R282.1 R302.2 R318.2 TP80.1(TP) U54.5(VCC) U56.3(VCCA) U56.12(PVIN_B3) U56.16(PVIN_B4) U56.18(VIO) U56.20(PVIN_LDO12) U56.30(PVIN_B2) U56.34(PVIN_B1) U57.10(VCC) ; also on sheet 2 13 14 32 43
VCC_3V3_MAIN_PG: U54.3(B) ; also on sheet 32 42
VCC_3V3_SYS: R288.1 R291.1 U56.9(VMON1) ; also on sheet 1 2 3 6 10 14 17 18 19 20 22 31 37 38 40 41 42 45 46 48 49 50 51 52 53 54 55 56 57 58
VCC_5V0: R543.1 ; also on sheet 6 14 31 32 51 52 54
VCC_CORE: C226.1 C227.1 C228.1 C229.1 C532.1 C533.1 C534.1 C535.1 C536.1 C537.1 L4.2 L5.2 R265.4 R577.1
VCC_CORE_N: R265.2 ; also on sheet 18
VCC_CORE_P: R265.3 ; also on sheet 18
VDD_0V85_N: R581.1 ; also on sheet 18
VDD_0V85_P: R581.4 ; also on sheet 18
VDD_1V8_N: R316.4 ; also on sheet 18
VDD_1V8_P: R316.1 ; also on sheet 18
VDD_CANUART: U47.H9(VDD_CANUART) ; also on sheet 14
VDD_CORE: C441.1 C445.1 C448.1 C460.1 C462.1 C468.1 C477.1 C494.1 C657.1(IN/OUT) C657.3(OUT/IN) C658.1(IN/OUT) C658.3(OUT/IN) C659.1(IN/OUT) C659.3(OUT/IN) C660.1(IN/OUT) C660.3(OUT/IN) C661.1(IN/OUT) C661.3(OUT/IN) C662.1(IN/OUT) C662.3(OUT/IN) C663.1(IN/OUT) C663.3(OUT/IN) R265.1 TP53.1(TP) U47.J9(VDD_CORE) U47.J11(VDD_CORE) U47.J13(VDD_CORE) U47.J15(VDD_CORE) U47.K14(VDD_CORE) U47.L9(VDD_CORE) U47.L11(VDD_CORE) U47.L13(VDD_CORE) U47.M12(VDD_CORE) U47.N11(VDD_CORE) U47.N13(VDD_CORE) U47.P10(VDD_CORE) U47.P14(VDD_CORE) U47.R9(VDD_CORE) U47.R15(VDD_CORE) U47.T16(VDD_CORE) U47.U15(VDD_CORE) U56.4(FB_B1) ; also on sheet 13
VDD_CORE_0V85: R577.2 R581.3 R587.2
VDD_CORE_REG_SW1: L4.1 U56.33(SW_B1)
VDD_CORE_REG_SW2: L5.1 U56.31(SW_B2)
VDD_LPDDR4: C522.1 C526.1 C530.1 C531.1 C664.1(IN/OUT) C664.3(OUT/IN) C665.1(IN/OUT) C665.3(OUT/IN) C666.1(IN/OUT) C666.3(OUT/IN) C667.1(IN/OUT) C667.3(OUT/IN) C668.1(IN/OUT) C668.3(OUT/IN) C669.1(IN/OUT) C669.3(OUT/IN) C670.1(IN/OUT) C670.3(OUT/IN) R327.4 TP83.1(TP) U47.A2(VDDS_DDR) U47.AA1(VDDS_DDR) U47.AB2(VDDS_DDR) U47.B1(VDDS_DDR) U47.J7(VDDS_DDR) U47.K8(VDDS_DDR) U47.L7(VDDS_DDR) U47.L8(VDDS_DDR_C) U47.M8(VDDS_DDR) U47.N7(VDDS_DDR) U47.P8(VDDS_DDR) U56.22(FB_B4) ; also on sheet 36
VDDA1V8: C254.1 R316.2 U56.19(VOUT_LDO1) ; also on sheet 48
VDDA_1V8: C198.1(IN/OUT) C198.3(OUT/IN) C202.1 C423.1 C424.1 C431.1 C439.1 C442.1(IN/OUT) C442.3(OUT/IN) C483.1 C486.1 R316.3 TP79.1(TP) U47.G18(VDDA_TEMP1) U47.L10(VDDA_TEMP2) U47.P16(VDDA_TEMP0) U47.T10(VDDA_1P8_USB) ; also on sheet 13
VDDA_1V8_FB1: U47.J10(VDDA_MCU) U47.K10(VDDA_PLL4) U47.K13(VDDA_PLL3) U47.M13(VDDA_PLL2) U47.N9(VDDA_PLL0) U47.R11(VDDA_PLL1) ; also on sheet 13
VDDA_1V8_FB2: U47.T12(VDDA_1P8_CSIRX0) ; also on sheet 13
VDDA_1V8_FB_OSC: U47.J8(VDDS_OSC0) ; also on sheet 13
VDDA_DDR_PLL0: U47.M9(VDDA_DDR_PLL0) ; also on sheet 13
VDDA_SYS_MON: C449.2 R543.2 R545.1 U47.H12(VMON_VSYS)
VDDR_CORE: C214.1(IN/OUT) C214.3(OUT/IN) C447.1 C465.1 C466.1 C481.1(IN/OUT) C481.3(OUT/IN) C490.1 C493.1 C505.1 R581.2 TP60.1(TP) U47.J14(VDDR_CORE) U47.K12(VDDR_CORE) U47.M10(VDDR_CORE) U47.M14(VDDR_CORE) U47.P9(VDDR_CORE) U47.P12(VDDR_CORE) ; also on sheet 2
VINT_LDO: C249.1 TP74.1(TP) U56.7(VOUT_LDOVINT)
 VDDA_CORE_CSI: U47.T11(VDDA_CORE_CSIRX0) ; also on sheet 13
 VDDA_CORE_USB: U47.T9(VDDA_CORE_USB) ; also on sheet 13
CAN_IO_3V3: R309.2 U47.H8(VDDSHV_CANUART) ; also on sheet 4 13
CAP_VDDS0: C454.1 U47.G13(CAP_VDDS0)
CAP_VDDS1: C434.1 U47.K16(CAP_VDDS1)
CAP_VDDS2: C446.1 U47.T14(CAP_VDDS2)
CAP_VDDS3: C432.1 U47.M16(CAP_VDDS3)
CAP_VDDS4: C507.1 U47.R8(CAP_VDDS4)
CAP_VDDS5: C443.1 U47.G15(CAP_VDDS5)
CAP_VDDS6: C435.1 U47.J16(CAP_VDDS6)
CAP_VDDS_CANUART: C509.1 U47.G8(CAP_VDDS_CANUART)
CAP_VDDS_MCU: C484.1 U47.G10(CAP_VDDS_MCU)
CORE_CONFIG: U56.8(GPIO3) ; also on sheet 2
MCU_I2C0_SCL: R296.1 ; also on sheet 48
MCU_I2C0_SDA: R294.1 ; also on sheet 48
MCU_INTn: R299.1 ; also on sheet 48
MCU_SAFETY_ERRORz_3V3: R281.1 ; also on sheet 10
PMIC_ADC_IN: TP84.1(TP) U56.11(GPIO5)
PMIC_EN: R317.2 U56.17(EN/PB/VSENSE)
PMIC_ENABLE: U54.6(C) U57.4(A)
PMIC_I2C_SCL: R297.2 TP72.1(TP) U56.1(SCL_I2C1/SCK_SPI)
PMIC_I2C_SDA: R307.2 TP73.1(TP) U56.2(SDA_I2C1/SDI_SPI)
PMIC_INT_B: R288.2 R299.2 R300.2 TP70.1(TP) U56.27(~{INT}/EN_DRV)
PMIC_INTn: R300.1 ; also on sheet 2
PMIC_LPM_EN0: R309.1 U57.3(A1) U57.8(B0) ; also on sheet 48
PMIC_LPM_SEL: J16.1 R318.1 U57.1(SEL)
PMIC_nSLEEP: U56.10(GPIO4) U57.6(B)
PMIC_POWERGOOD: R290.1 ; also on sheet 10
PMIC_RSTOUT: R290.2 R291.2 TP67.1(TP) U56.28(~{RSTOUT}) ; also on sheet 2
SOC_DVDD1V8: C196.1(IN/OUT) C196.3(OUT/IN) C200.1 C422.1(IN/OUT) C422.3(OUT/IN) C426.1 C429.1 C433.1 C437.1 C440.1 C444.1 C453.1 C457.1 C461.1 C502.1 C506.1 R334.3 TP86.1(TP) U47.F12(VMON_1P8_SOC) U47.G14(VDDSHV0) U47.H13(VDDSHV0) U47.H16(VDDSHV6) U47.H17(VDDSHV6) U47.K15(VDDSHV1) U47.L15(VDDSHV3) U47.L16(VDDSHV1) U47.M15(VDDSHV3) U47.N15(VDDSHV3) U47.T8(VDDSHV4) U47.U8(VDDSHV4) U56.24(FB_B3) ; also on sheet 36
SoC_DVDD3V3: C210.1(IN/OUT) C210.3(OUT/IN) C450.1 C451.1 C452.1 C458.1 C471.1 C476.1 C482.1(IN/OUT) C482.3(OUT/IN) U47.F9(VMON_3P3_SOC) U47.G11(VDDSHV_MCU) U47.H10(VDDSHV_MCU) U47.R13(VDDSHV2) U47.T13(VDDSHV2) U47.U10(VDDA_3P3_USB) U47.U13(VDDSHV2) ; also on sheet 13 14
SoC_VDDSHV5_SDIO: U47.G16(VDDSHV5) U47.H15(VDDSHV5) ; also on sheet 13
TEST_POWERDOWN: U54.1(A) ; also on sheet 3 32
TPS65224_EN: Q4.2(S) R303.1 R317.1 TP81.1(TP)
VPP_1V8: U47.F7(VPP) ; also on sheet 13 14
WD_DISABLE: R281.2 R282.2 TP56.1(TP) U56.29(GPIO6)
WKUP_I2C0_SCL: R297.1 ; also on sheet 48
WKUP_I2C0_SDA: R307.1 ; also on sheet 48
ZENER_CLAMP: D2.3(C) R298.1 R308.1
N24305910: R296.2 U56.36(GPIO2)
N24305927: R294.2 U56.35(GPIO1)
N24306091: R293.1 U54.4(Y)
N24306101: Q4.1(G) R293.2
N24306157: D5.3(K) R308.2
N24306190: Q4.3(D) R298.2
N24307593: R302.1 U57.2(A0) U57.7(B1)

Not connected (* = marked no-connect by the designer): D2 2(NC)*; U47 F10(RSVD4)

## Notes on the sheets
sheet 33
- SOC POWER SUPPLY PMIC - 1
- Route as Pseudo differential pair trace
  from Load (Remote Sense)
- Vz = 5V
- (See "PCB Notes")
- FB_VDD_CORE_P
- FB_VDD_CORE_N
- Silk: PMIC
- PMIC uses default I2C1 ADDR: 0x48,0x49, 0x4A, 0x4B
- When VDD_CORE = 0.75V
  Depopulate R577 & Populate R587
- Silk: PMIC_LPM_SEL
- PMIC Config option
- Silk: PMIC_PROG
sheet 34
- SOC POWER SUPPLIES AND SUPPLY RAILS
- 0.5V to VMON_SYS pin
- SOC VSS
sheet 35
- SOC POWER SUPPLIES - DECAPS 1
- Place 0.1uF cap near SoC Balls
- Place 0.1uF cap near SoC Balls
- Place 0.1uF cap near SoC Balls
- Place 0.1uF cap near SoC Balls
- Place 0.1uF cap near SoC Balls
- Place 0.1uF cap near SoC Balls
